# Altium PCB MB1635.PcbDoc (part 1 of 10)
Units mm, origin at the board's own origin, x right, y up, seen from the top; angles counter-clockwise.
Board outline 127 x 97 mm, 6 copper layers (Top Layer, Signal Layer 1, Signal Layer 2, Signal Layer 3, Signal Layer 4, Bottom Layer), stack 1.557 mm thick; 593 components, 478 nets, 2435 pads, 1743 vias.
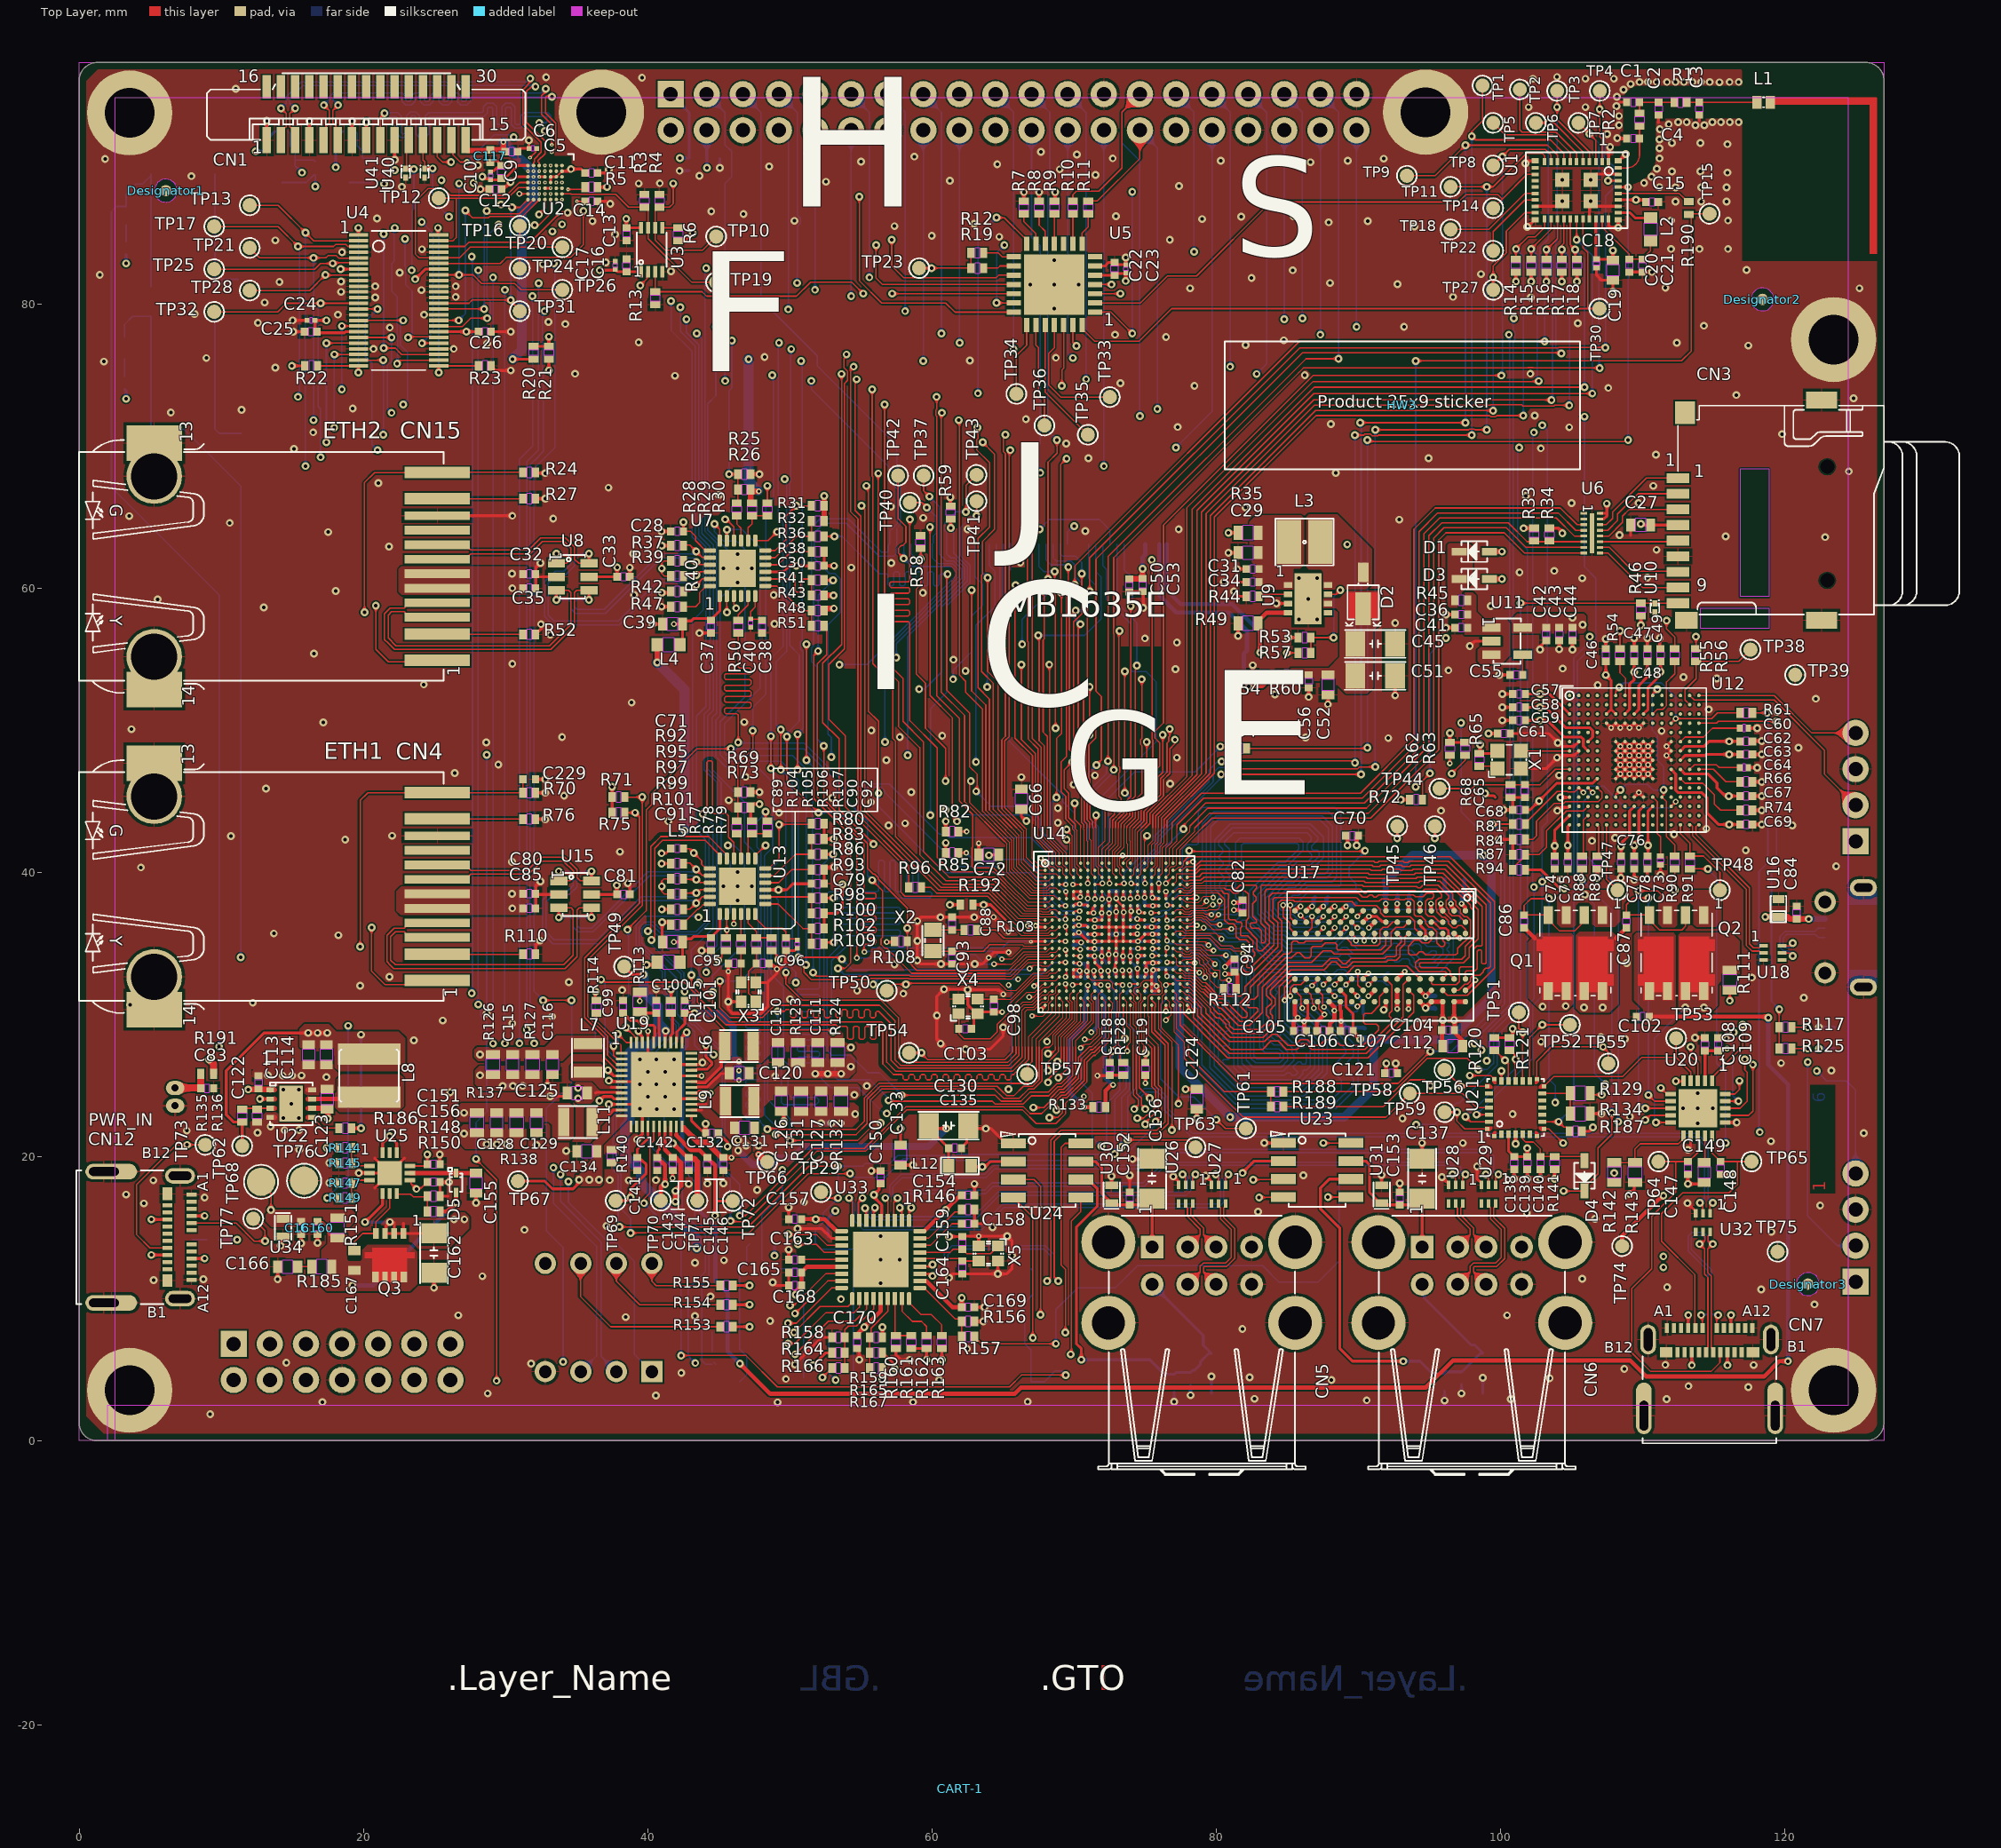
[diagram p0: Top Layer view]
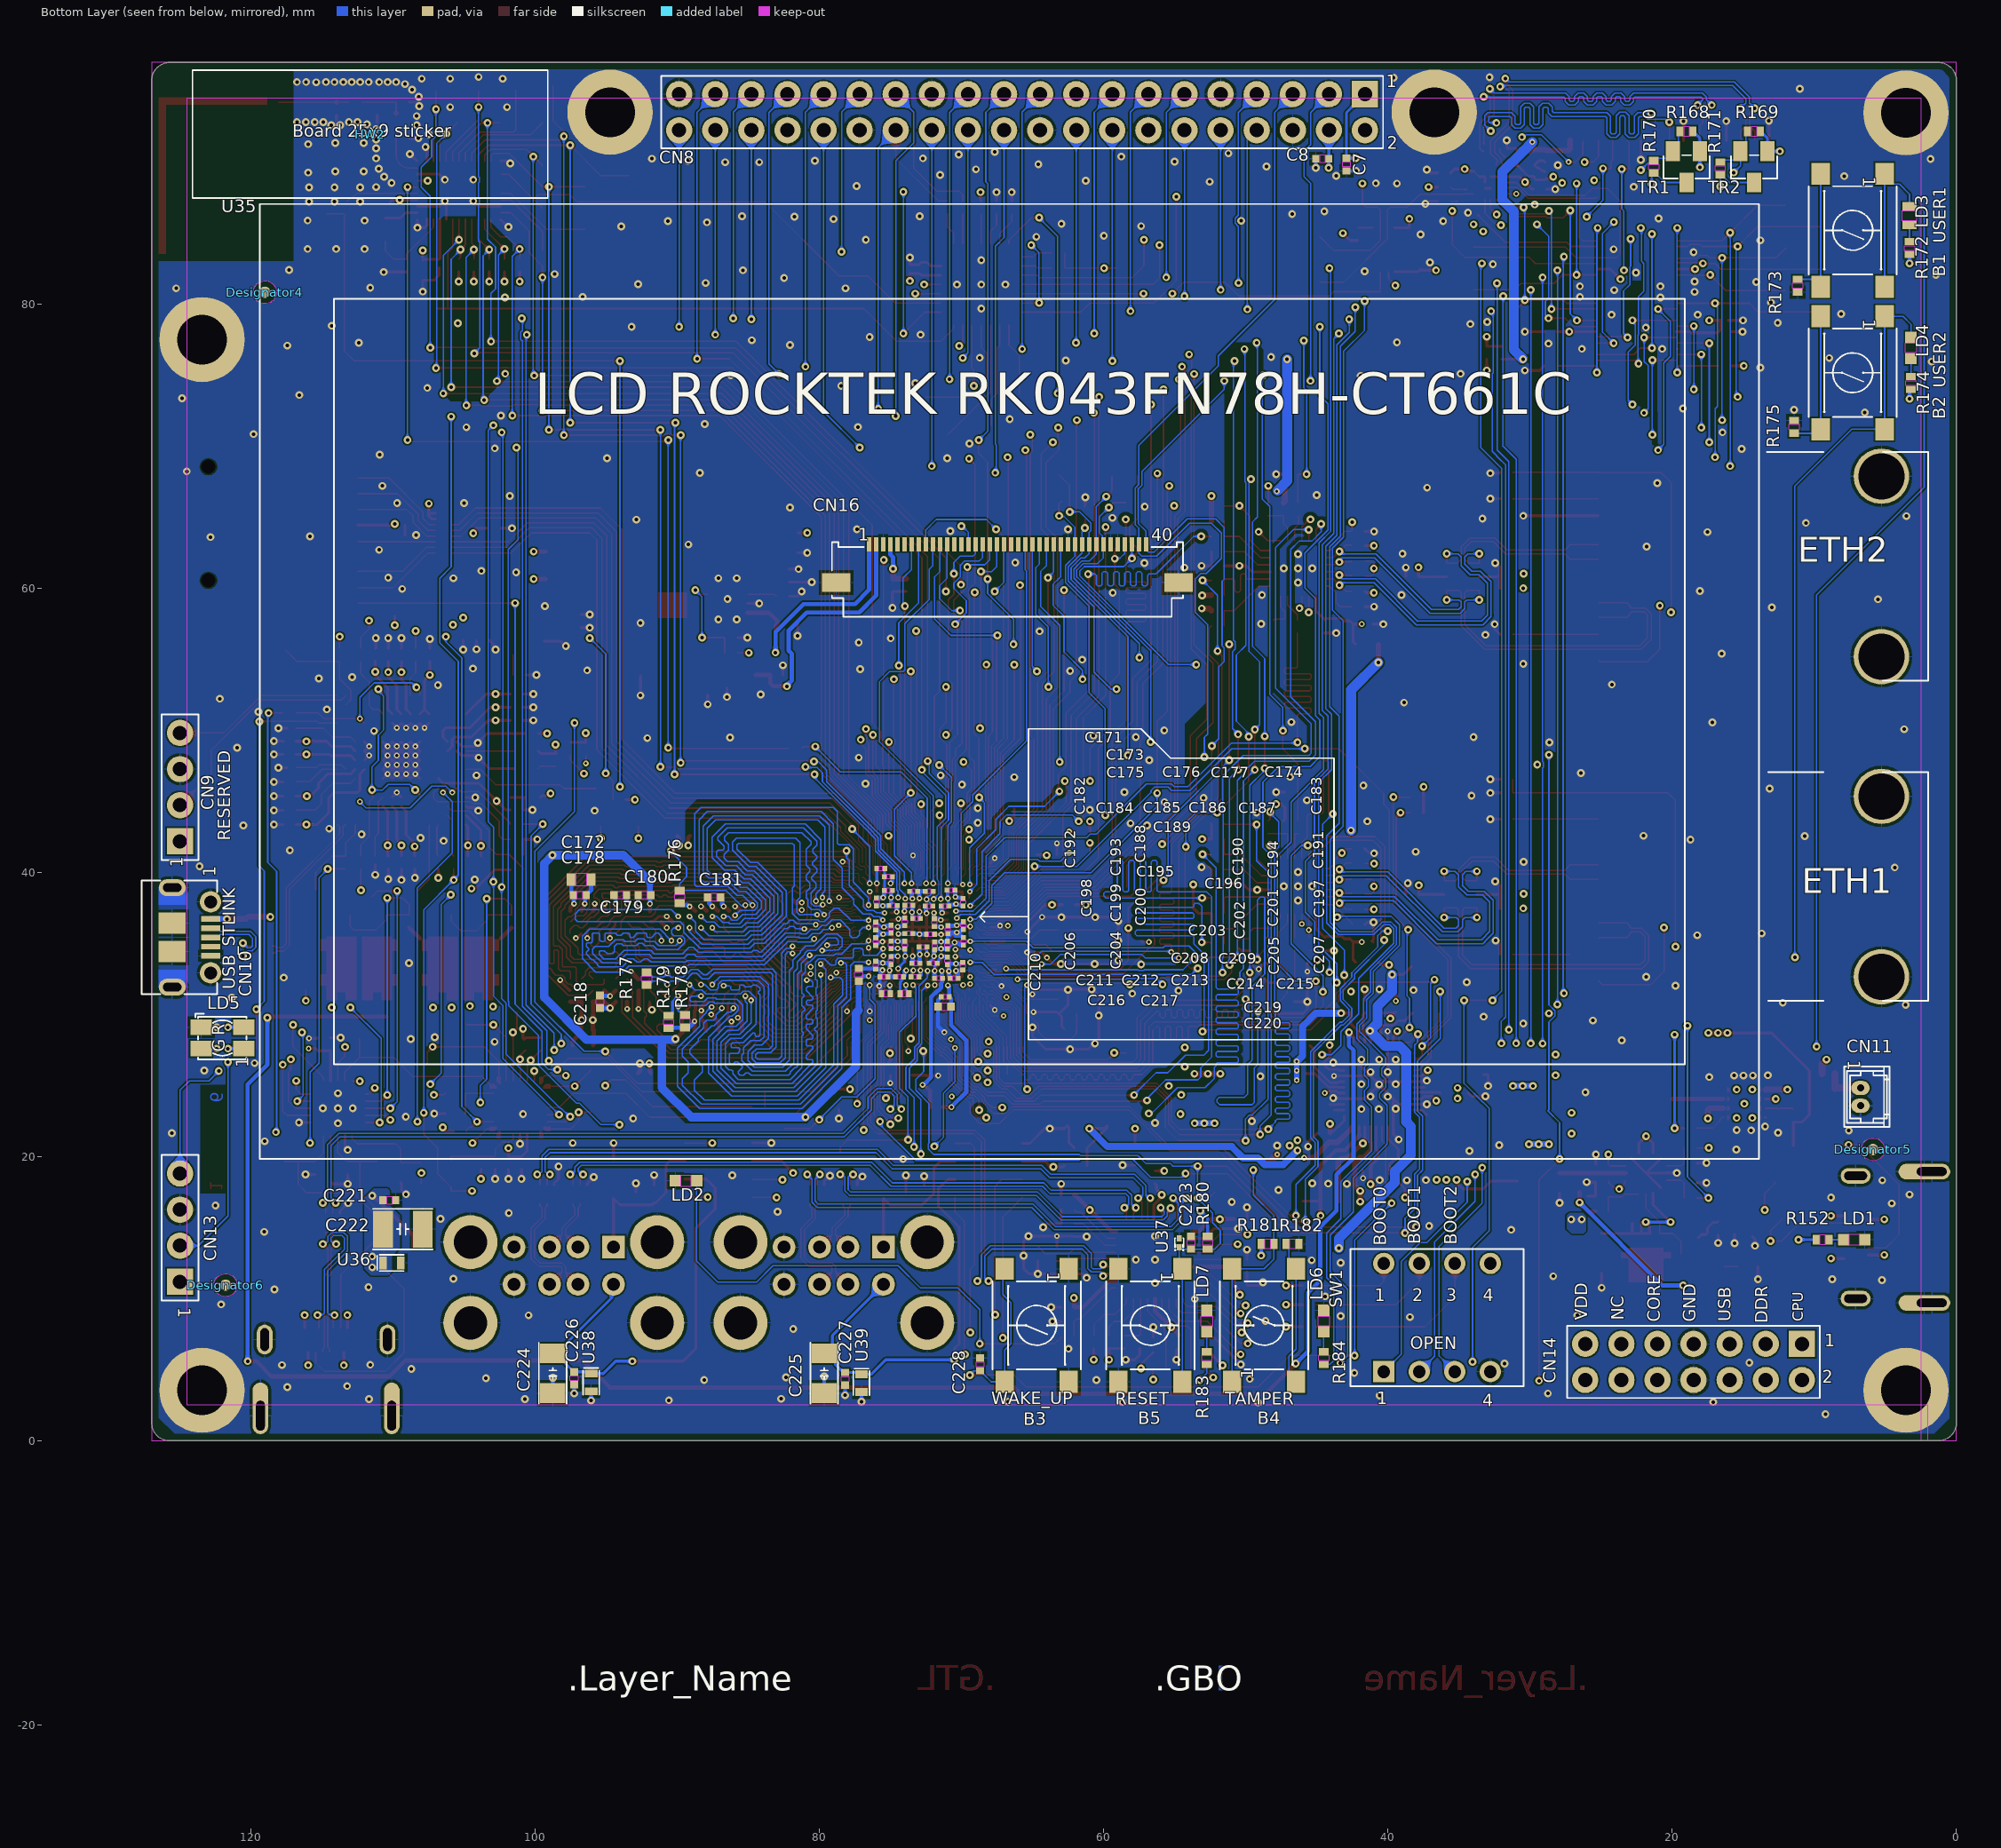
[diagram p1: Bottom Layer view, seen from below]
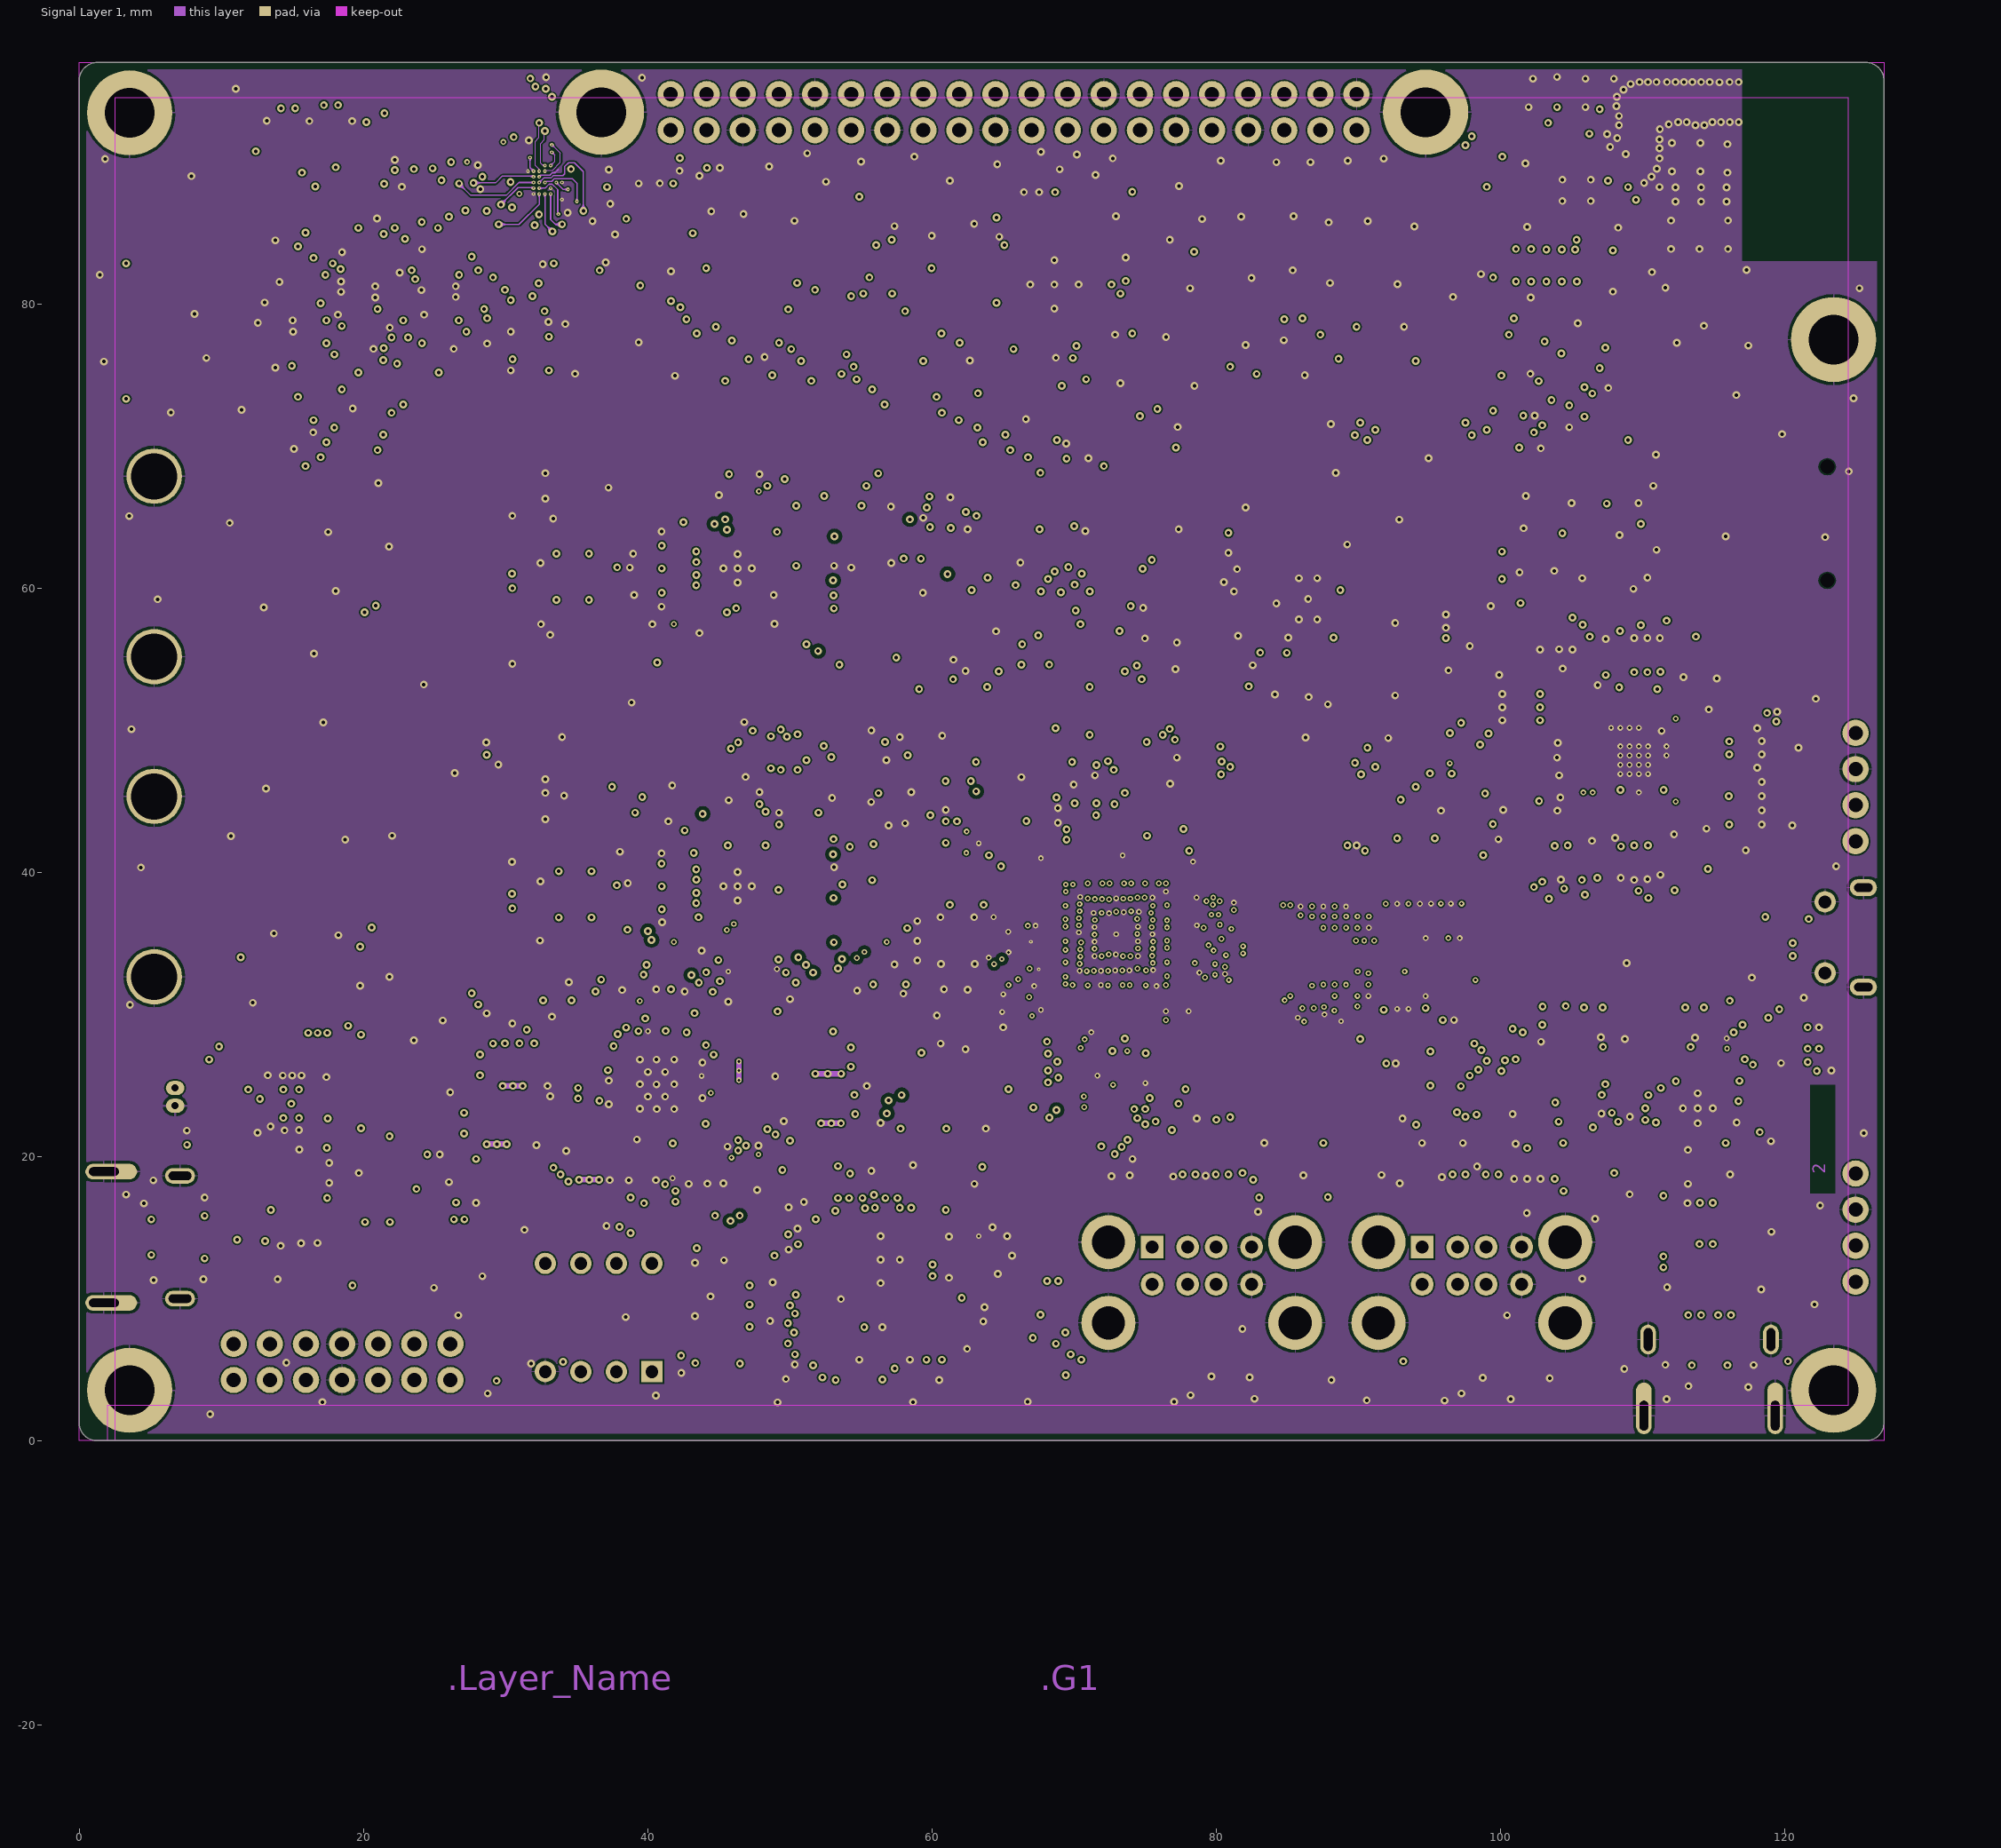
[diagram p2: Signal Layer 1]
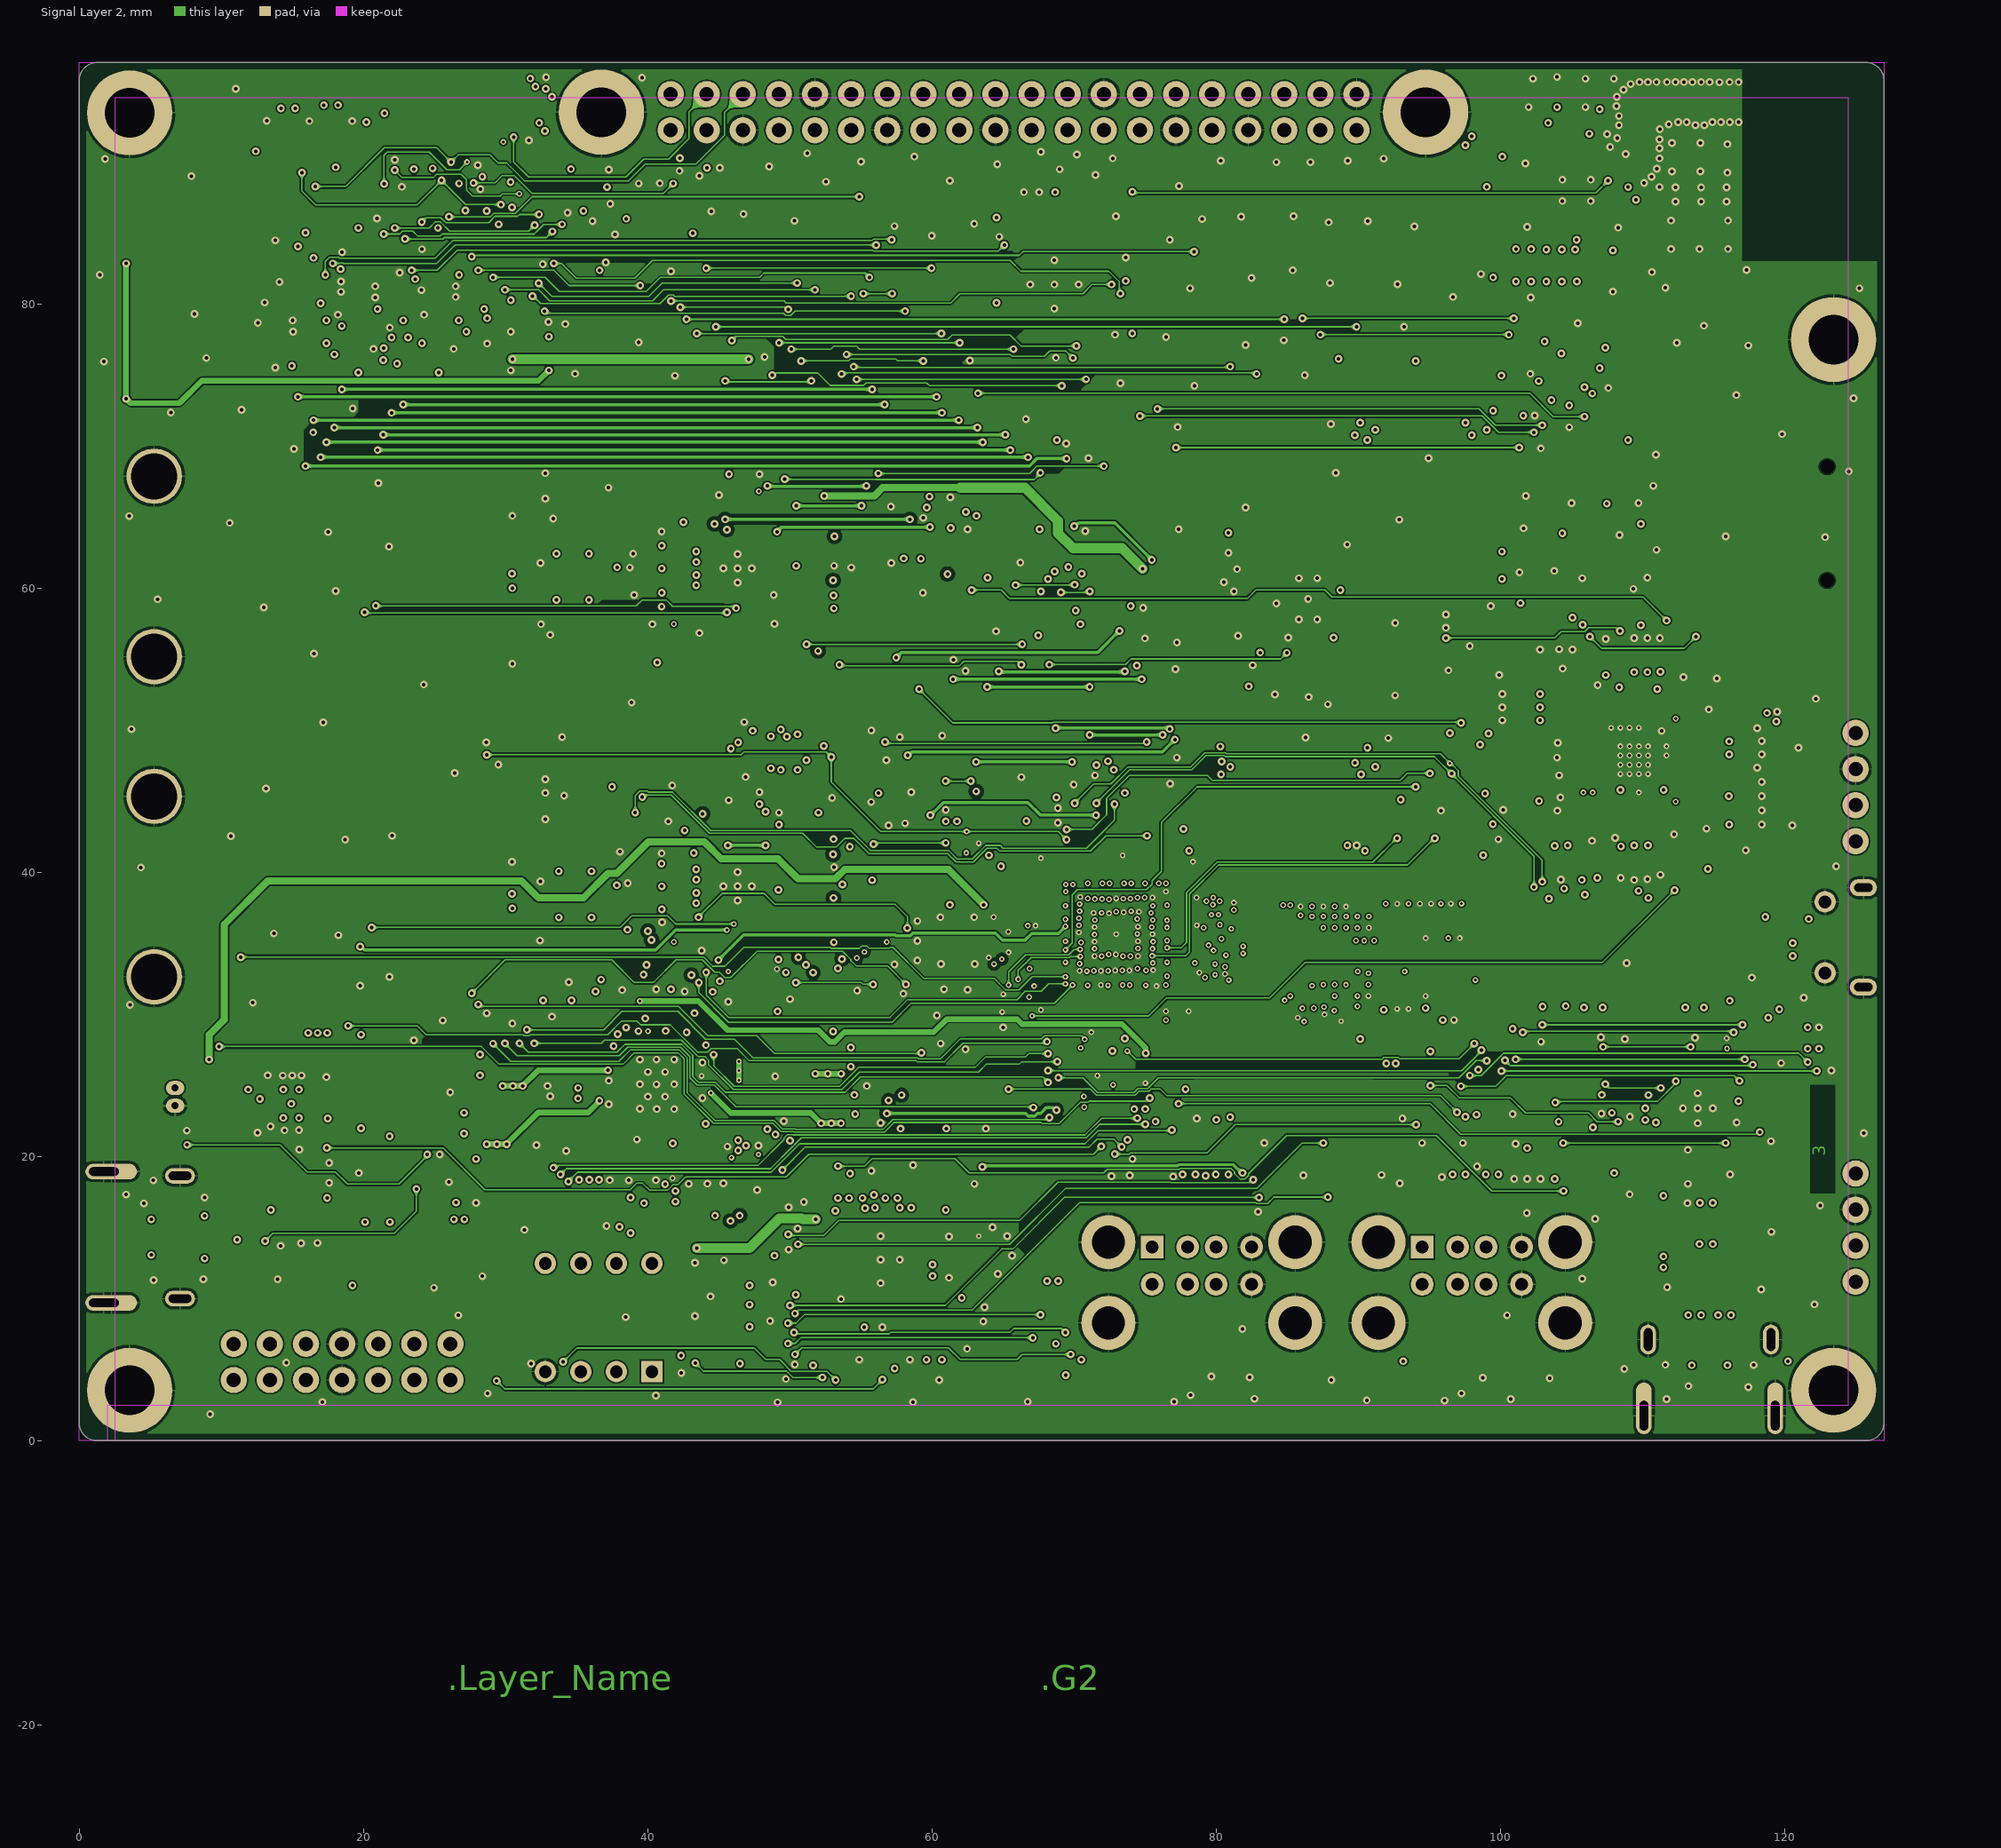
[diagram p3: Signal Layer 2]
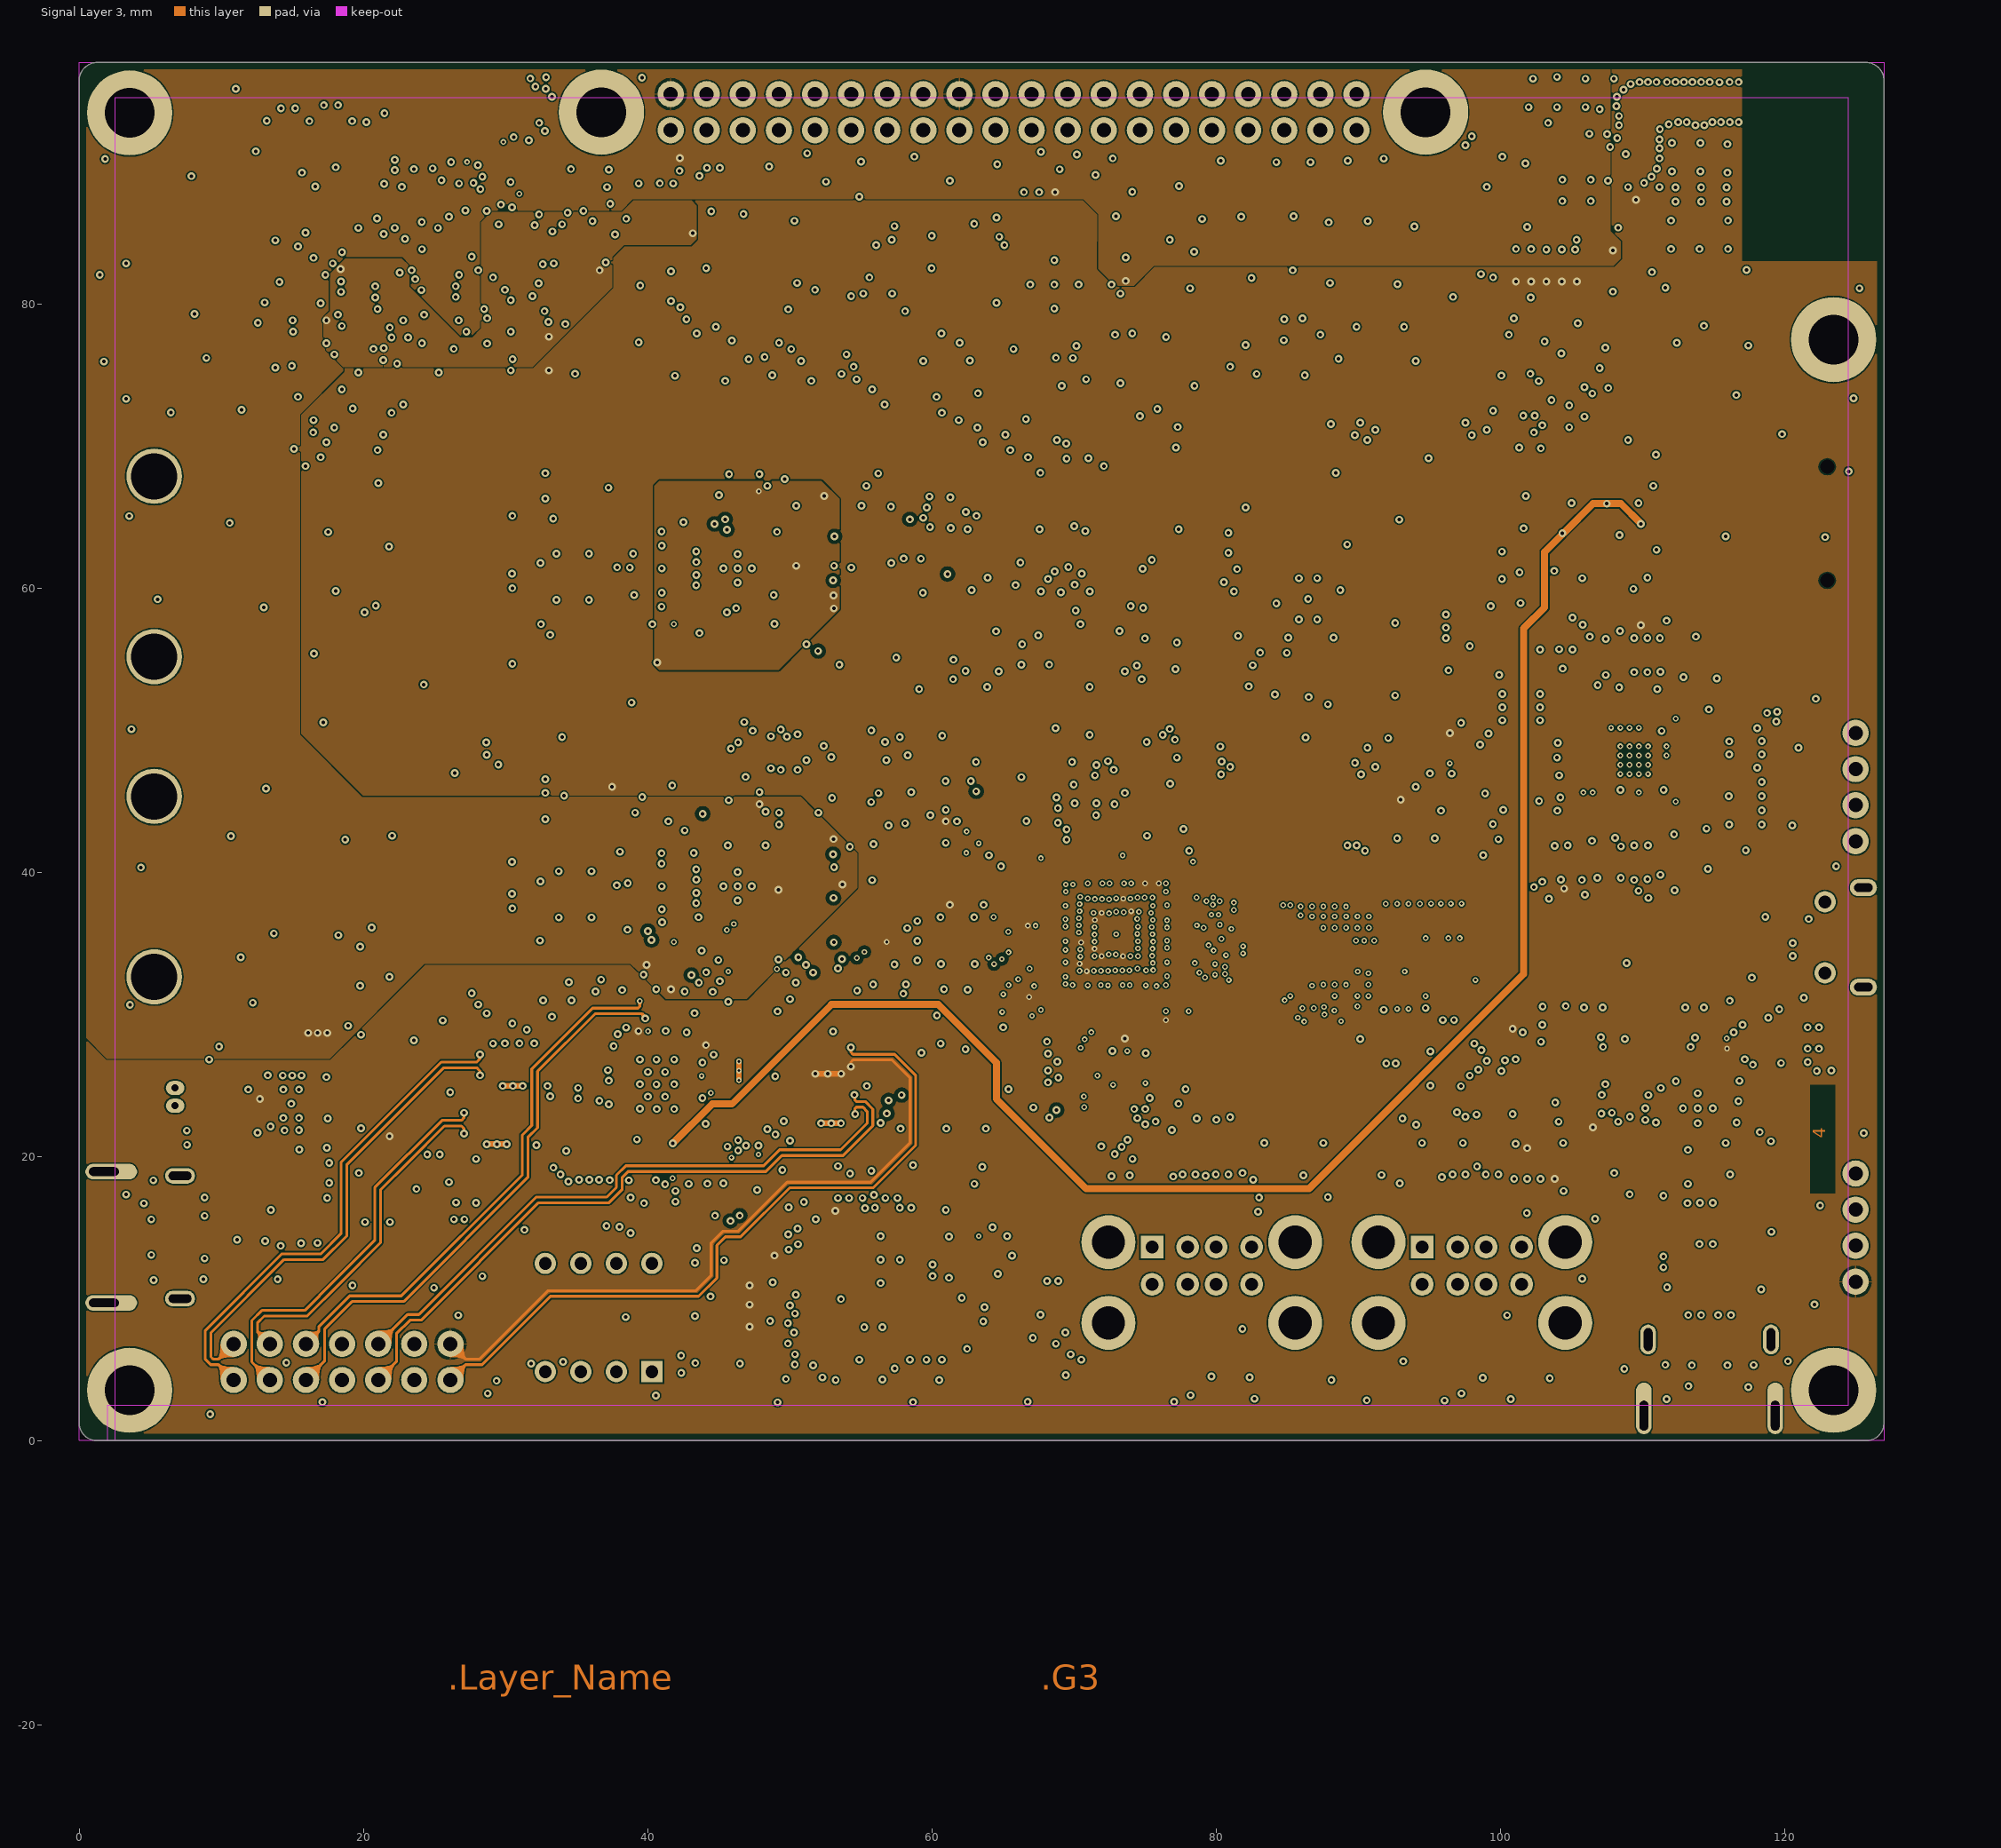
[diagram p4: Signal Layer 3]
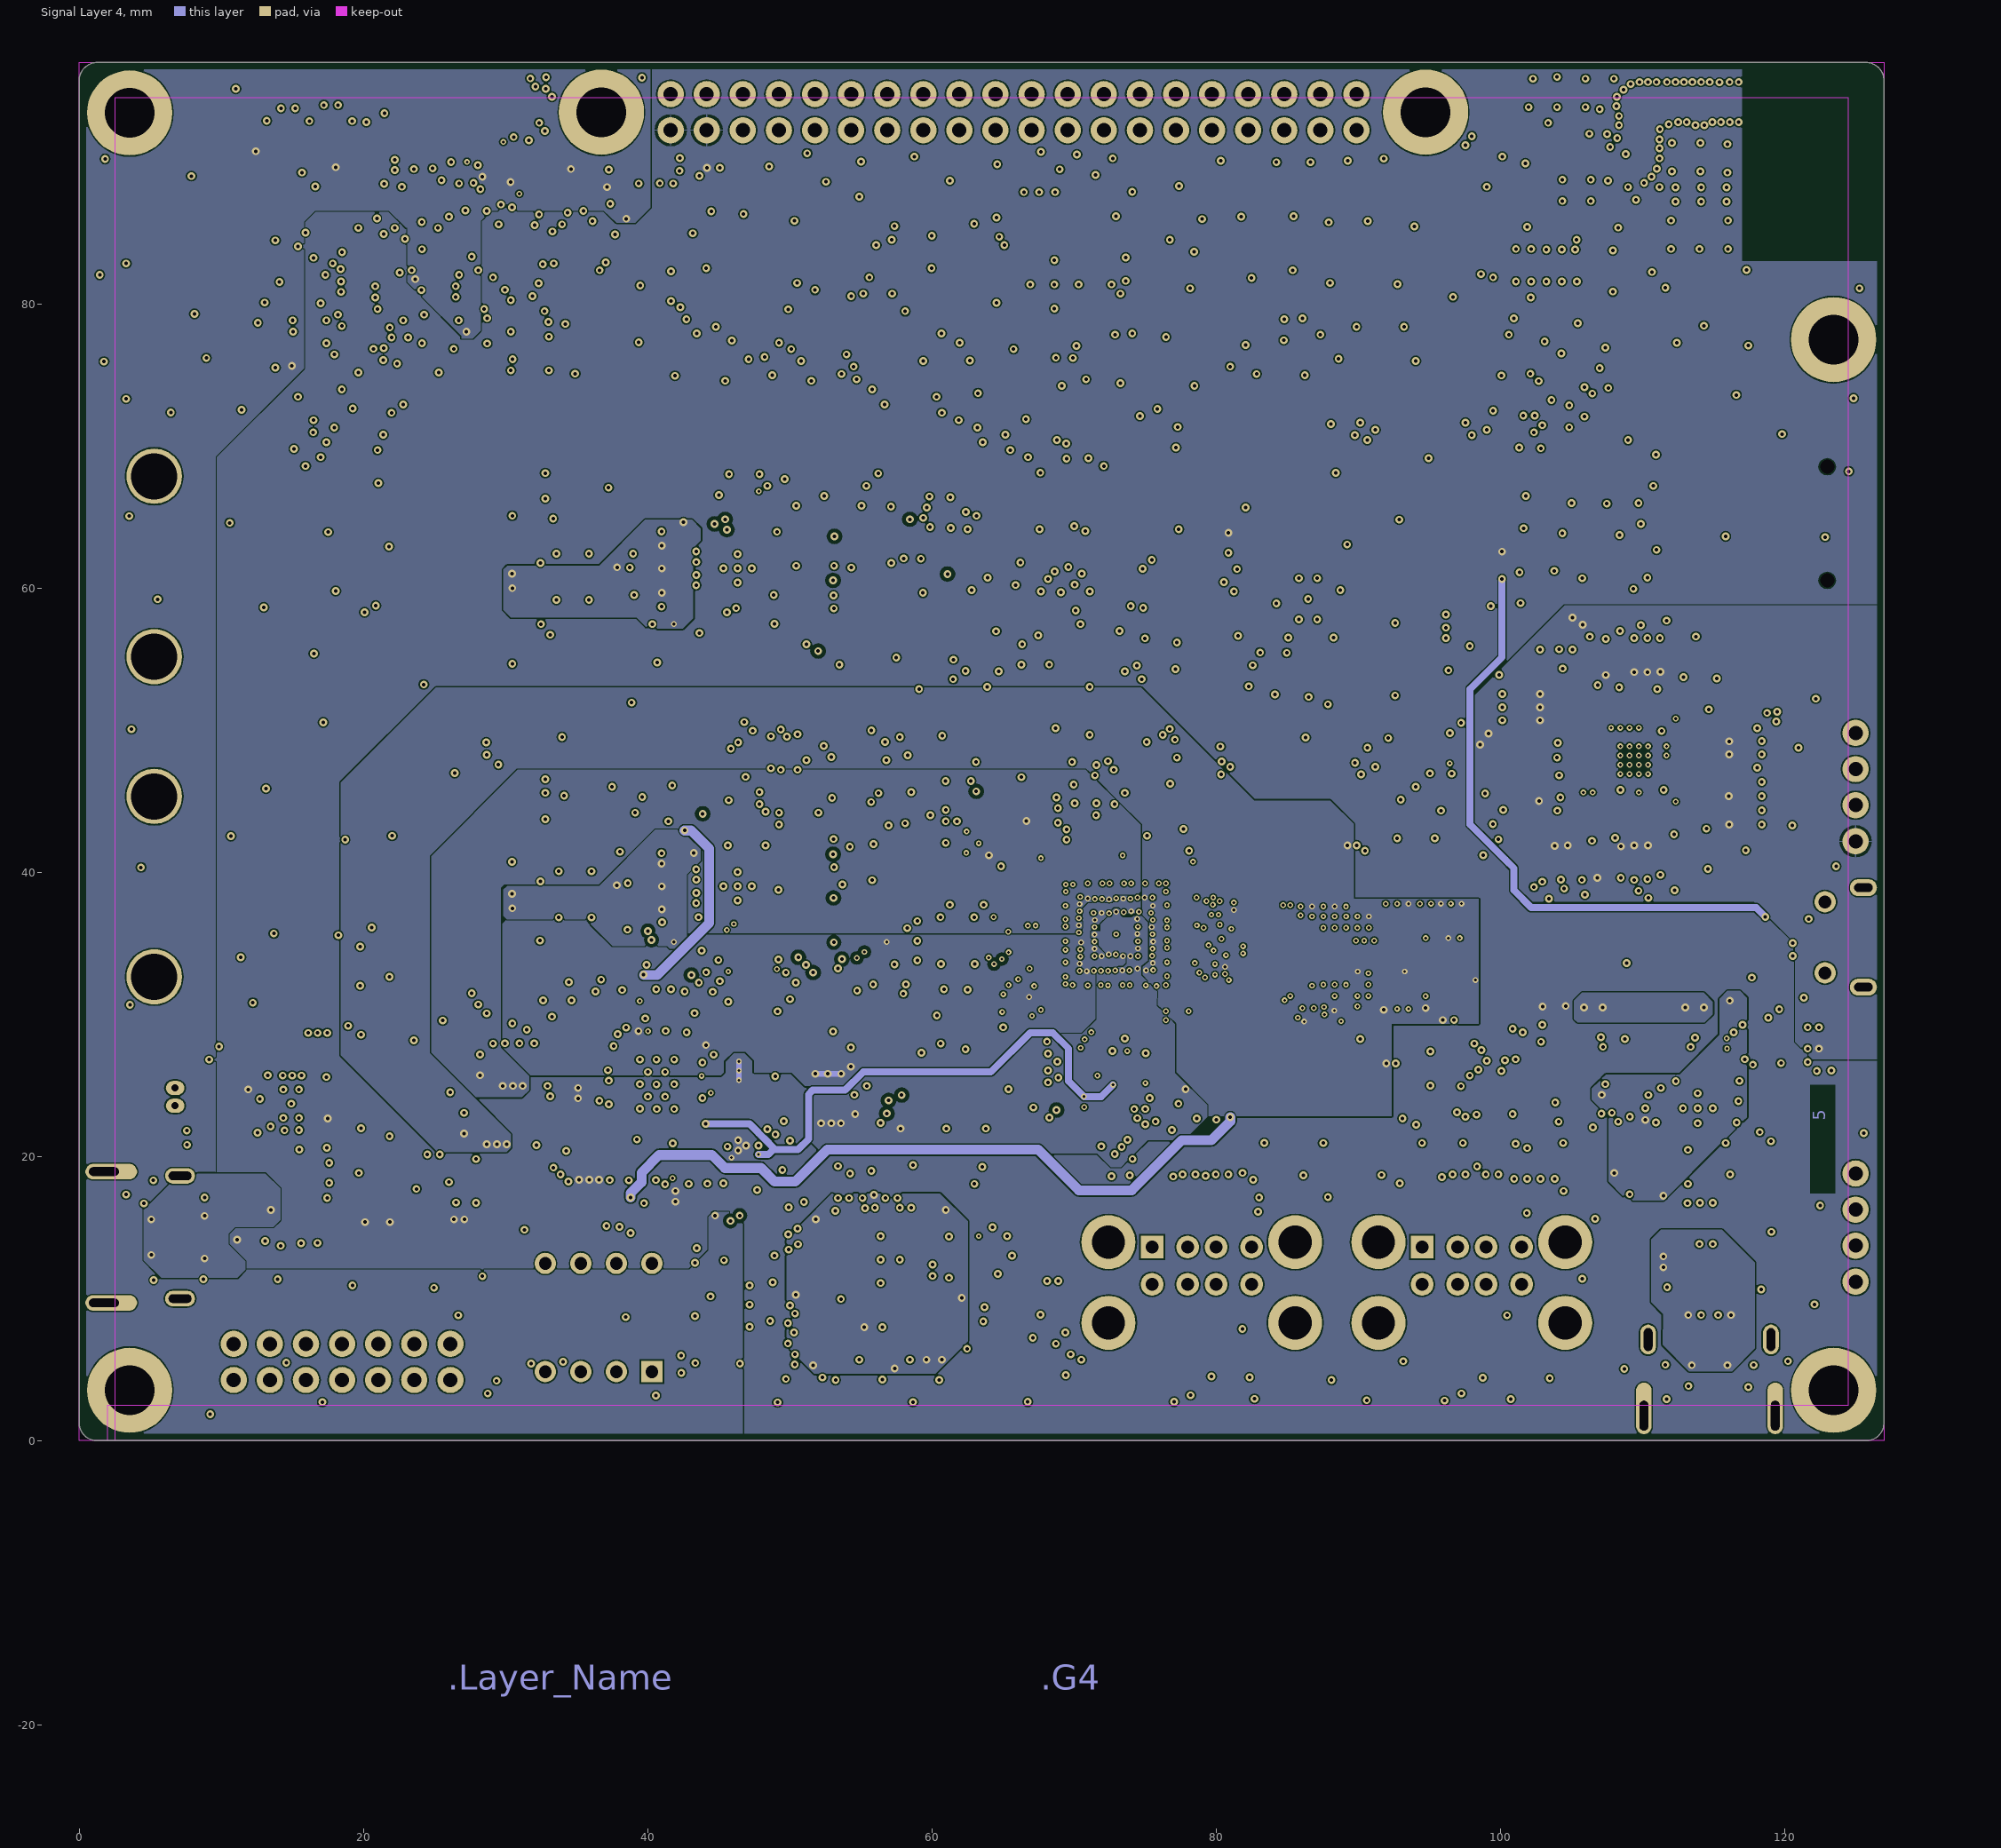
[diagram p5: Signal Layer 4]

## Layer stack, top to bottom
Top Solder: solder mask 0.025, Solder Resist, Dk 3.5
Top Layer: signal copper 0.027
Dielectric 1: prepreg 0.068, Dk 4
Signal Layer 1: signal copper 0.033
Dielectric 2: prepreg 0.51, Dk 4
Signal Layer 2: signal copper 0.033
Dielectric 3: core 0.215, Dk 5
Signal Layer 3: signal copper 0.033
Dielectric 4: prepreg 0.51, Dk 4
Signal Layer 4: signal copper 0.033
Dielectric5: prepreg 0.068, Dk 4
Bottom Layer: signal copper 0.027
Bottom Solder: solder mask 0.025, Solder Resist, Dk 3.5

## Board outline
0,1.27 0,95.73 cw(c1.27,95.73) 1.27,97 125.73,97 cw(c125.73,95.73) 127,95.73 127,1.27 cw(c125.73,1.27) 125.73,0 1.27,0 cw(c1.27,1.27)

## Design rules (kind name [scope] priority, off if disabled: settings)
BoardOutlineClearance [All] p1: gap=0.5 ignorepadtopadclearanceinfootprint=FALSE except(0: Arc-SplitContinuation Track-SplitContinuation SMDPad-SplitContinuation THPad-SplitContinuation Via-SplitContinuation Fill-SplitContinuation Poly-SplitContinuation Region-SplitContinuation Text-SplitContinuation)
Clearance Clearance_keepout_copper [KeepoutRestrictionsCopper] p1: gap=0 ignorepadtopadclearanceinfootprint=FALSE except(0.1: SMDPad-Fill SMDPad-Poly SMDPad-Region Fill-Fill Fill-Poly Fill-Region Poly-Poly Poly-Region Region-Region)
Clearance Clearance_keepout_track [KeepoutRestrictionsTrack] p2: gap=0 ignorepadtopadclearanceinfootprint=FALSE except(0.1: SMDPad-Fill SMDPad-Poly SMDPad-Region Fill-Fill Fill-Poly Fill-Region Poly-Poly Poly-Region Region-Region)
Clearance Clearance_MCU [WithinRoom('RoomDefinition')and TouchesRoom('RoomDefinition')] p3: gap=0.094 ignorepadtopadclearanceinfootprint=FALSE except(0: Arc-Hole Track-Hole SMDPad-Hole THPad-Hole Via-Hole Fill-Hole Poly-Hole Region-Hole Text-Hole; 0.1: Via-Via)
Clearance Clearance_DDR [WithinRoom('RoomDefinition_1')and TouchesRoom('RoomDefinition_1')] p4: gap=0.094 ignorepadtopadclearanceinfootprint=FALSE except(0: Arc-Hole Track-Hole SMDPad-Hole THPad-Hole Via-Hole Fill-Hole Poly-Hole Region-Hole Text-Hole; 0.1: Via-Via)
Clearance Clearance_SDMMC1 [InNetClass('SDMMC1') vs InNetClass('All Nets')] p5: gap=0.1 ignorepadtopadclearanceinfootprint=FALSE except(0: Arc-Hole Track-Hole SMDPad-Hole THPad-Hole Via-Hole Fill-Hole Poly-Hole Region-Hole Text-Hole; 0.15: Arc-Fill Track-Fill SMDPad-Fill THPad-Fill Via-Fill Fill-Fill; 0.2: THPad-THPad; 0.25: Track-Track)
Clearance Clearance_RGMII [InNetClass('RGMII_ETH_RXD_TXD')] p6: gap=0.1 ignorepadtopadclearanceinfootprint=FALSE except(0: Arc-Hole Track-Hole SMDPad-Hole THPad-Hole Via-Hole Fill-Hole Poly-Hole Region-Hole Text-Hole; 0.15: Arc-Fill Arc-Region Track-Fill Track-Region SMDPad-Fill SMDPad-Region THPad-Fill THPad-Region Via-Fill Via-Region Fill-Fill Fill-Region Poly-Region Region-Region; 0.2: Arc-THPad Track-THPad SMDPad-SMDPad SMDPad-THPad THPad-THPad; 0.26: Arc-Poly Track-Poly SMDPad-Poly THPad-Poly Via-Poly Fill-Poly Poly-Poly)
Clearance [All] p7: gap=0.1 ignorepadtopadclearanceinfootprint=FALSE except(0: Arc-Hole Track-Hole SMDPad-Hole THPad-Hole Via-Hole Fill-Hole Poly-Hole Region-Hole Text-Hole; 0.15: Arc-Fill Track-Fill SMDPad-Fill THPad-Fill Via-Fill Fill-Fill; 0.2: THPad-THPad)
ComponentClearance [HasFootprint('TP_SMD_1MM') vs HasFootprint('No Footprint')] p1: gap=0.2 collisioncheckmode=3 verticalgap=0.2 showdistances=FALSE
DiffPairsRouting I_SENSE [InDifferentialPairClass('I_SENSE')] p1: maxlimit=0.2 minlimit=0.2 mostfreqgap=0.2 toplayer_minwidth=0.09 toplayer_maxwidth=0.4 toplayer_prefwidth=0.2 midlayer1_minwidth=0.09 midlayer1_maxwidth=0.4 midlayer1_prefwidth=0.2 midlayer2_minwidth=0.09 midlayer2_maxwidth=0.4 midlayer2_prefwidth=0.2 midlayer3_minwidth=0.09 midlayer3_maxwidth=0.4 midlayer3_prefwidth=0.2 midlayer4_minwidth=0.09 midlayer4_maxwidth=0.4 midlayer4_prefwidth=0.2 bottomlayer_minwidth=0.09 bottomlayer_maxwidth=0.4 bottomlayer_prefwidth=0.2 maxuncoupledlength=12.7
DiffPairsRouting DiffPairsRouting_DIFF_100Ohms [InDifferentialPairClass('Diff_100Ohms')] p2: maxlimit=0.3 minlimit=0.127 mostfreqgap=0.3 toplayer_mingap=0.17 toplayer_maxgap=0.17 toplayer_prefgap=0.17 toplayer_minwidth=0.09 toplayer_maxwidth=0.09 toplayer_prefwidth=0.09 midlayer1_mingap=0.25 midlayer1_minwidth=0.075 midlayer1_maxwidth=0.075 midlayer1_prefwidth=0.075 midlayer2_maxgap=0.127 midlayer2_prefgap=0.127 midlayer2_minwidth=0.075 midlayer2_maxwidth=0.075 midlayer2_prefwidth=0.075 midlayer3_maxgap=0.127 midlayer3_prefgap=0.127 midlayer3_minwidth=0.075 midlayer3_maxwidth=0.075 midlayer3_prefwidth=0.075 midlayer4_mingap=0.3 midlayer4_minwidth=0.075 midlayer4_maxwidth=0.075 midlayer4_prefwidth=0.075 bottomlayer_mingap=0.17 bottomlayer_maxgap=0.17 bottomlayer_prefgap=0.17 bottomlayer_minwidth=0.09 bottomlayer_maxwidth=0.09 bottomlayer_prefwidth=0.09 impedanceprofiledriven=TRUE impedanceprofileid={5577E63A-EB22-4F3A-99DF-7BFE230ABC16} impedanceprofilevalue=100.000000 maxuncoupledlength=12.7
DiffPairsRouting DiffPairsRouting_USB_90Ohms [InDifferentialPairClass('USB_90Ohms')] p3: maxlimit=0.13 minlimit=0.127 mostfreqgap=0.127 toplayer_mingap=0.13 toplayer_prefgap=0.13 toplayer_minwidth=0.1 toplayer_maxwidth=0.1 toplayer_prefwidth=0.1 midlayer1_maxgap=0.127 midlayer1_minwidth=0.066 midlayer1_maxwidth=0.066 midlayer1_prefwidth=0.066 midlayer2_maxgap=0.127 midlayer2_minwidth=0.113 midlayer2_maxwidth=0.113 midlayer2_prefwidth=0.113 midlayer3_maxgap=0.127 midlayer3_minwidth=0.113 midlayer3_maxwidth=0.113 midlayer3_prefwidth=0.113 midlayer4_maxgap=0.127 midlayer4_minwidth=0.066 midlayer4_maxwidth=0.066 midlayer4_prefwidth=0.066 bottomlayer_mingap=0.13 bottomlayer_prefgap=0.13 bottomlayer_minwidth=0.1 bottomlayer_maxwidth=0.1 bottomlayer_prefwidth=0.1 impedanceprofiledriven=TRUE impedanceprofileid={A0CE1C67-AEA5-4110-ADE4-376356967360} impedanceprofilevalue=90.000000 maxuncoupledlength=12.7
FanoutControl Fanout_BGA [IsBGA] p1: bgadir=Out bgaviamode=Closest fanoutstyle=Auto fanoutdirection=Alternating viagrid=0.025 // Fanout_BGA (Default Rule)
FanoutControl Fanout_LCC [IsLCC] p2: bgadir=Out bgaviamode=Closest fanoutstyle=Auto fanoutdirection=Alternating viagrid=0.025 // Fanout_LCC (Default Rule)
FanoutControl Fanout_SOIC [IsSOIC] p3: bgadir=Out bgaviamode=Closest fanoutstyle=Auto fanoutdirection=Alternating viagrid=0.025 // Fanout_SOIC (Default Rule)
FanoutControl Fanout_Small [(CompPinCount < 5)] p4: bgadir=Out bgaviamode=Closest fanoutstyle=Auto fanoutdirection=OutThenIn viagrid=0.025 // Fanout_Small (Default Rule)
FanoutControl Fanout_Default [All] p5: bgadir=Out bgaviamode=Closest fanoutstyle=Auto fanoutdirection=Alternating viagrid=0.025 // Fanout_Default (Default Rule)
HoleSize [All] p1: absolutevalues=TRUE maxlimit=10 minlimit=0.025 maxpercent=80.000 minpercent=20.000
HoleToHoleClearance [All] p1: gap=0.25 allowstackedmicrovias=TRUE
Length Length_SDMMC1 [InNetClass('SDMMC1')] p1: maxlimit=100 minlimit=0
MatchedLengths "Schematic Matched Net Lengths_9" [InNetClass('LCD_R[2..7]')] p1: tolerance=2.54 checknetsindiffpair=FALSE checkdiffpairvsdiffpair=TRUE checkxsignals=TRUE checkothers=TRUE
MatchedLengths "Schematic Matched Net Lengths_8" [InNetClass('LCD_B[2..7]')] p2: tolerance=2.54 checknetsindiffpair=FALSE checkdiffpairvsdiffpair=TRUE checkxsignals=TRUE checkothers=TRUE
MatchedLengths "Schematic Matched Net Lengths_7" [InNetClass('LCD_G[2..7]')] p3: tolerance=2.54 checknetsindiffpair=FALSE checkdiffpairvsdiffpair=TRUE checkxsignals=TRUE checkothers=TRUE
MatchedLengths "Schematic Matched Net Lengths_6" [InNet('LCD_VSYNC')] p4: tolerance=2.54 checknetsindiffpair=FALSE checkdiffpairvsdiffpair=TRUE checkxsignals=TRUE checkothers=TRUE
MatchedLengths "Schematic Matched Net Lengths_5" [InNet('LCD_CLK')] p5: tolerance=2.54 checknetsindiffpair=FALSE checkdiffpairvsdiffpair=TRUE checkxsignals=TRUE checkothers=TRUE
MatchedLengths "Schematic Matched Net Lengths_4" [InNet('LCD_HSYNC')] p6: tolerance=2.54 checknetsindiffpair=FALSE checkdiffpairvsdiffpair=TRUE checkxsignals=TRUE checkothers=TRUE
MatchedLengths "Schematic Matched Net Lengths_3" [InNet('USB_DEV_HS_CN_N')] p7: tolerance=2 checknetsindiffpair=TRUE checkdiffpairvsdiffpair=FALSE checkxsignals=FALSE checkothers=FALSE
MatchedLengths "Schematic Matched Net Lengths_2" [InNet('USB_DEV_HS_N')] p8: tolerance=2 checknetsindiffpair=TRUE checkdiffpairvsdiffpair=FALSE checkxsignals=FALSE checkothers=FALSE
MatchedLengths "Schematic Matched Net Lengths_1" [InNet('USB_DEV_HS_CN_P')] p9: tolerance=2 checknetsindiffpair=TRUE checkdiffpairvsdiffpair=FALSE checkxsignals=FALSE checkothers=FALSE
MatchedLengths "Schematic Matched Net Lengths" [InNet('USB_DEV_HS_P')] p10: tolerance=2 checknetsindiffpair=TRUE checkdiffpairvsdiffpair=FALSE checkxsignals=FALSE checkothers=FALSE
MatchedLengths MatchedLengths_ETH1 [InxSignalClass('RGMII_ETH1')] p11: tolerance=10 checknetsindiffpair=FALSE checkdiffpairvsdiffpair=TRUE checkxsignals=TRUE checkothers=TRUE
MatchedLengths MatchedLengths_ETH2 [InxSignalClass('RGMII_ETH2')] p12: tolerance=10 checknetsindiffpair=FALSE checkdiffpairvsdiffpair=TRUE checkxsignals=TRUE checkothers=TRUE
MatchedLengths MatchedLengths_SDMMC1 [InxSignalClass('SDMMC1')] p13: tolerance=5 checknetsindiffpair=FALSE checkdiffpairvsdiffpair=TRUE checkxsignals=TRUE checkothers=TRUE
MaxMinImpedance "Schematic Impedance Constraint_7" [InNet('USB_DEV_HS_N')] p1: minimum=85.00 maximum=95.00
MaxMinImpedance "Schematic Impedance Constraint_6" [InNet('USB_DEV_HS_CN_P')] p2: minimum=85.00 maximum=95.00
MaxMinImpedance "Schematic Impedance Constraint_5" [InNet('USB_DEV_HS_P')] p3: minimum=85.00 maximum=95.00
MaxMinImpedance "Schematic Impedance Constraint_4" [InNet('USB_DEV_HS_CN_N')] p4: minimum=85.00 maximum=95.00
MaxMinImpedance "Schematic Impedance Constraint_3" [InNet('USB_DEV_HS_CN_P')] p5: minimum=85.00 maximum=95.00
MaxMinImpedance "Schematic Impedance Constraint_1" [InNet('USB_DEV_HS_CN_N')] p6: minimum=85.00 maximum=95.00
MaxMinImpedance "Schematic Impedance Constraint_2" [InNet('USB_DEV_HS_N')] p7: minimum=85.00 maximum=95.00
MaxMinImpedance "Schematic Impedance Constraint" [InNet('USB_DEV_HS_P')] p8: minimum=85.00 maximum=95.00
MinimumSolderMaskSliver [All] p1: minsoldermaskwidth=0.1
PlaneConnect [All] p1: planeconnectstyle=Relief reliefexpansion=0.508 reliefentries=4 reliefconductorwidth=0.21 reliefairgap=0.21
PolygonConnect PolygonConnect_NO_FT [IsNamedPolygon('NO_FT')] p1: connectstyle=Direct reliefconductorwidth=0.254 reliefentries=4 polygonreliefangle="90 Angle" airgapwidth=0.254
PolygonConnect [All] p2: thpad.connectstyle=Relief thpad.reliefconductorwidth=0.1 thpad.reliefentries=4 thpad.polygonreliefangle="90 Angle" thpad.airgapwidth=0.2 smdpad.connectstyle=Relief smdpad.reliefconductorwidth=0.1 smdpad.reliefentries=4 smdpad.polygonreliefangle="90 Angle" smdpad.airgapwidth=0.2 via.connectstyle=Direct via.reliefconductorwidth=0.2 via.reliefentries=4 via.polygonreliefangle="90 Angle" via.airgapwidth=0.2
RoomDefinition [InComponentClass('Room Definition 1') vs False] p1: confinementstyle=ConfineIn formatcopy=TRUE lockcomponents=FALSE outline 65.175,43.125 81.275,43.125 81.275,27.725 65.175,27.725
RoomDefinition RoomDefinition_1 [InComponentClass('Components Class 1')] p2: confinementstyle=ConfineIn formatcopy=TRUE lockcomponents=FALSE outline 74.9,40.7 79.1,44.9 88.375,44.9 92.175,41.1 97.15,41.1 99.625,38.625 99.625,31.4 96.4,28.175 92.85,28.175 91.025,26.35 91.025,24.625 89.425,23.025 81,23.025 77.638,26.388 77.638,29.884 74.9,32.621
RoutingVias [All] p1: holewidth=0.2 width=0.4 viastyle="Through Hole" minholewidth=0.1 minwidth=0.2 maxholewidth=0.35 maxwidth=0.55
ShortCircuit ShortCircuit_LNK2 [InPadClass('LNK2')] p1: allowed=TRUE
ShortCircuit ShortCircuit_LNK1 [InPadClass('LNK1')] p2: allowed=TRUE
ShortCircuit [All] p3: allowed=FALSE
SilkToSilkClearance [All] p1: silktosilkclearance=0.2
SilkToSolderMaskClearance [IsPad] p1: minsilkscreentomaskgap=0.2 clearancetoexposedcopper=TRUE
SolderMaskExpansion [All] p1: expansion=0.1 istentingtop=FALSE
Width Width_MCU [WithinRoom('RoomDefinition')and TouchesRoom('RoomDefinition')] p1: maxlimit=10 minlimit=0.075 preferedwidth=0.09 toplayer_prefwidth=0.075 minimp=50.000000 maximp=50.000000 favimp=50.000000
Width Width_50Ohms [InNetClass('50_Ohms')] p2: maxlimit=0.219 minlimit=0.077 preferedwidth=0.219 toplayer_minwidth=0.1 toplayer_maxwidth=0.1 toplayer_prefwidth=0.1 midlayer1_maxwidth=0.077 midlayer1_prefwidth=0.077 midlayer2_minwidth=0.219 midlayer3_minwidth=0.219 midlayer4_maxwidth=0.077 midlayer4_prefwidth=0.077 bottomlayer_minwidth=0.1 bottomlayer_maxwidth=0.1 bottomlayer_prefwidth=0.1 impedanceprofiledriven=TRUE impedanceprofileid={CEAE712B-4FFB-4667-9AAD-FAB2F10F3795} impedanceprofilevalue=50.000000 minimp=50.000000 maximp=50.000000 favimp=50.000000
Width Width_ALIMS [InNetClass('ALIMS')] p3: maxlimit=10 minlimit=0.09 preferedwidth=0.2
Width [All] p4: maxlimit=10 minlimit=0.075 preferedwidth=0.1
16 further rules are at their usual default settings.

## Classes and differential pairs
component class U_USB_TypeC_DRP: TP78
component class U_Peripherals: HW1301 HW1302 HW1303
net class LTDC: LCD_B2 LCD_B3 LCD_B4 LCD_B5 LCD_B6 LCD_B7 LCD_CLK LCD_G2 LCD_G3 LCD_G4 LCD_G5 LCD_G6 LCD_G7 LCD_HSYNC LCD_R2 LCD_R3 LCD_R4 LCD_R5 LCD_R6 LCD_R7 LCD_VSYNC
net class 50_Ohms: DCMI_D0 DCMI_D1 DCMI_D2 DCMI_D3 DCMI_D4 DCMI_D5 DCMI_D6 DCMI_D7 DCMI_HSYNC DCMI_PIXCLK DCMI_VSYNC ETH1_CLK ETH1_CRS_DV ETH1_MDC ETH1_MDINT ETH1_MDIO ETH1_RX_CLK ETH1_RXD0 ETH1_RXD1 ETH1_TX_EN ETH1_TXD0 ETH1_TXD1 ETH2_CLK ETH2_CRS_DV ETH2_MDC ETH2_MDINT ETH2_MDIO ETH2_RXD0 ETH2_RXD1 ETH2_TX_EN ETH2_TXD0 ETH2_TXD1 LCD_B2 LCD_B3 LCD_B4 LCD_B5 LCD_B6 LCD_B7 LCD_CLK LCD_G2 LCD_G3 LCD_G4 LCD_G5 LCD_G6 LCD_G7 LCD_HSYNC LCD_R2 LCD_R3 LCD_R4 LCD_R5 LCD_R6 LCD_R7 LCD_VSYNC NetC229_2 NetCN3_1 NetCN3_2 NetCN3_5 NetCN3_7 NetCN3_8 NetR29_1 NetR32_1 NetR41_2 NetR48_1 NetR50_2 NetR78_1 NetR83_1 NetR98_2 NetR102_1 NetR106_2 SDMMC1_CK SDMMC1_D0 SDMMC1_D1 SDMMC1_D2 SDMMC1_D3 SDMMC2_CK SDMMC2_D0 SDMMC2_D1 SDMMC2_D2 SDMMC2_D3 T_SWCLK T_SWDIO T_SWO
net class ALIMS: 1V8_PERIPH 3V3_AO 3V3_STLK 3V3_SW 5V_USB_CHGR 5V_VIN GND NetC83_2 VDD VDD_ADC VDD_CORE VDD_CPU VDD_DDR VDD_LS VDD_SD VDD_USB VREF_DDR
differential pair class USB_90Ohms: USB1CN25 USB2CN25 USB3CN26 USB4CN26 USB_D1 USB_D2 USB_DCONN USB_DEV_HS USB_DEV_HS_CN USBDN1 USBDN2 USBDN3 USBDN4
net class SDMMC1: NetCN3_1 NetCN3_2 NetCN3_5 NetCN3_7 NetCN3_8 SDMMC1_CK SDMMC1_D0 SDMMC1_D1 SDMMC1_D2 SDMMC1_D3
net class RGMII_ETH_RXD_TXD: ETH1_CRS_DV ETH1_RXD0 ETH1_RXD1 ETH1_TX_EN ETH1_TXD0 ETH1_TXD1 ETH2_CRS_DV ETH2_RXD0 ETH2_RXD1 ETH2_TX_EN ETH2_TXD0 ETH2_TXD1
net class RGMII_ETH1: ETH1_CLK ETH1_CRS_DV ETH1_MDC ETH1_MDINT ETH1_MDIO ETH1_RX_CLK ETH1_RXD0 ETH1_RXD1 ETH1_TX_EN ETH1_TXD0 ETH1_TXD1 NetC229_2 NetR78_1 NetR83_1 NetR98_2 NetR102_1 NetR106_2
net class RGMII_ETH2: ETH2_CLK ETH2_CRS_DV ETH2_MDC ETH2_MDINT ETH2_MDIO ETH2_RXD0 ETH2_RXD1 ETH2_TX_EN ETH2_TXD0 ETH2_TXD1 NetR29_1 NetR32_1 NetR41_2 NetR48_1 NetR50_2
differential pair class Diff_100Ohms: CLK1 DATA1 DATA2 DDR_CLK DDR_DQS0 DDR_DQS1 RD1 RD2 TD1 TD2
differential pair CLK1: +CLK_P -CLK_N
differential pair DATA2: +DATA2_P -DATA2_N
differential pair DATA1: +DATA1_P -DATA1_N
differential pair USB_D1: +USB_D1_P -USB_D1_N
differential pair USBDN4: +USBDN4_P -USBDN4_N
differential pair USBDN3: +USBDN3_P -USBDN3_N
differential pair USBDN2: +USBDN2_P -USBDN2_N
differential pair USBDN1: +USBDN1_P -USBDN1_N
differential pair USB_DEV_HS: +USB_DEV_HS_P -USB_DEV_HS_N
differential pair USB_DEV_HS_CN: +USB_DEV_HS_CN_P -USB_DEV_HS_CN_N
differential pair USB_DCONN: +USB_DCONN_P -USB_DCONN_N
differential pair USB_D2: +USB_D2_P -USB_D2_N
differential pair USB4CN26: +USB4CN26_P -USB4CN26_N
differential pair USB3CN26: +USB3CN26_P -USB3CN26_N
differential pair USB2CN25: +USB2CN25_P -USB2CN25_N
differential pair USB1CN25: +USB1CN25_P -USB1CN25_N
differential pair TD2: +TD2_P -TD2_N
differential pair TD1: +TD1_P -TD1_N
differential pair RD2: +RD2_P -RD2_N
differential pair RD1: +RD1_P -RD1_N
differential pair DDR_DQS1: +DDR_DQS1_P -DDR_DQS1_N
differential pair DDR_DQS0: +DDR_DQS0_P -DDR_DQS0_N
differential pair DDR_CLK: +DDR_CLK_P -DDR_CLK_N

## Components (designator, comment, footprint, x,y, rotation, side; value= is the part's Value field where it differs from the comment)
B1 "SW_PUSH_SMD" SWI_KNITTER_TSS644S 7.305,85.188 r270 bottom value=SW-PUSH-TSS644S
B2 "SW_PUSH_SMD" SWI_KNITTER_TSS644S 7.305,75.163 r270 bottom value=SW-PUSH-TSS644S
B3 "SW_PUSH_SMD" SWI_KNITTER_TSS644S 64.725,8.125 r270 bottom value=SW-PUSH-TSS644S
B4 "SW_PUSH_SMD" SWI_KNITTER_TSS644S 48.725,8.125 r90 bottom locked value=SW-PUSH-TSS644S
B5 "SW_PUSH_SMD" SWI_KNITTER_TSS644S 56.725,8.125 r270 bottom locked value=SW-PUSH-TSS644S
C1 "Capacitor" C0402#1 109.35,94.2 r0 top value=12pF
C2 "Capacitor" C0402#1 111.15,93.75 r90 top value=12pF
C3 "Capacitor" C0402#1 114,93.75 r90 top value=12pF
C4 "Capacitor" C0402#1 109.35,91.65 r0 top value=12pF
C5 "Capacitor" C0201_MURATA_GRM033_H0P3 31.925,90.95 r0 top value=1uF
C6 "Capacitor" C0402#1 30.425,90.725 r180 top value=1uF
C7 "Capacitor" C0402#1 42.925,89.825 r270 bottom value=100nF
C8 "Capacitor" C0402#1 44.625,90.225 r180 bottom value=100nF
C9 "Capacitor" C0402#1 29.7,89.3 r270 top value=100nF
C10 "Capacitor" C0201_MURATA_GRM033_H0P3 28.95,89.02 r270 top value=1uF
C11 "Capacitor" C0402#1 36.05,89.225 r180 top value=100nF
C12 "Capacitor" C0402#1 29.3,88.075 r0 top value=100nF
C13 "Capacitor" C0402#1 38.515,84.915 r90 top value=100nF
C14 "Capacitor" C0402#1 36.05,87.225 r180 top value=10nF
C15 "Capacitor" C0402#1 110.675,87.175 r180 top value=100nF
C16 "Capacitor" C0402#1 38.515,82.715 r270 top value=100nF
C17 "Capacitor" C0201_MURATA_GRM033_H0P3 37.715,82.715 r270 top value=1uF
C18 "Capacitor" C0201_H0P5 106.775,82.85 r90 top value=2.2uF
C19 "Capacitor" C0603 107.925,82.375 r90 top value=10uF
C20 "Capacitor" C0402#1 109.075,82.7 r90 top value=4.7uF
C21 "Capacitor" C0402#1 110,82.7 r90 top value=4.7uF
C22 "Capacitor" C0402#1 72.85,82.475 r270 top value=100nF
C23 "Capacitor" C0201_MURATA_GRM033_H0P3 73.65,82.475 r270 top value=1uF
C24 "Capacitor" C0201_MURATA_GRM033_H0P3 16.325,78.85 r0 top value=1uF
C25 "Capacitor" C0402#1 16.3,78.05 r0 top value=100nF
C26 "Capacitor" C0402#1 28.55,78.05 r180 top value=100nF
C27 "Capacitor" C0603 109.875,64.45 r0 top value=10uF
C28 "Capacitor" C0402#1 42.075,64 r0 top value=100nF
C29 "Capacitor" C0603 82.25,62.5 r180 top value=10uF
C30 "Capacitor" C0402#1 51.975,61.575 r180 top value=100nF
C31 "Capacitor" C0402#1 82.575,61.35 r0 top value=100nF
C32 "Capacitor" C0402#1 31.675,61 r180 top value=100nF
C33 "Capacitor" C0402#1 38.3,60.8 r0 top value=100nF
C34 "Capacitor" C0402#1 82.575,60.425 r0 top value=10nF
C35 "Capacitor" C0402#1 31.675,60 r180 top value=100nF
C36 "Capacitor" C0402#1 97.25,58.15 r180 top value=1uF
C37 "Capacitor" C0402#1 44.45,57.3 r90 top value=100nF
C38 "Capacitor" C0402#1 48.05,57.3 r90 top value=470pF
C39 "Capacitor" C0603 41.75,57.475 r180 top value=10uF
C40 "Capacitor" C0201_MURATA_GRM033_H0P3 47.25,57.55 r90 top value=1uF
C41 "Capacitor" C0402#1 97.25,57.225 r0 top value=100nF
C42 "Capacitor" C0402#1 103.225,56.775 r90 top value=4.7uF
C43 "Capacitor" C0402#1 104.15,56.775 r90 top value=1uF
C44 "Capacitor" C0402#1 105.075,56.775 r90 top value=100nF
C45 "Capacitor" C1206_H1P25 91.2,56.075 r180 top value=4.7uF
C46 "Capacitor" C0402#1 107.425,55.3 r270 top value=100nF
C47 "Capacitor" C0402#1 109.425,55.3 r270 top value=100nF
C48 "Capacitor" C0402#1 110.35,55.3 r270 top value=100nF
C49 "Capacitor" C0402#1 111.275,55.3 r270 top value=100nF
C50 "Capacitor" C0402#1 73.895,60.2 r270 top value=4.7uF
C51 "Capacitor" C1206_H1P25 91.2,53.825 r180 top value=4.7uF
C52 "Capacitor" C0603 87.875,53.2 r90 top value=100nF
C53 "Capacitor" C0402#1 74.825,60.225 r90 top value=100nF
C54 "Capacitor" C0402#1 83.025,53.9 r0 top value=10nF
C55 "Capacitor" C0402#1 101.125,53.9 r0 top value=10nF
C56 "Capacitor" C0402#1 86.525,53.45 r90 top value=33pF
C57 "Capacitor" C0402#1 101.325,52.55 r0 top value=100nF
C58 "Capacitor" C0402#1 101.325,51.625 r0 top value=100nF
C59 "Capacitor" C0402#1 101.325,50.7 r0 top value=100nF
C60 "Capacitor" C0201_H0P5 117.15,50.15 r180 top value=2.2uF
C61 "Capacitor" C0402#1 100.25,49.775 r180 top value=100nF
C62 "Capacitor" C0402#1 117.3,49.225 r180 top value=100nF
C63 "Capacitor" C0402#1 117.3,48.3 r180 top value=100nF
C64 "Capacitor" C0201_H0P5 117.15,47.375 r180 top value=2.2uF
C65 "Capacitor" C0402#1 101.725,45.725 r90 top value=100nF
C66 "Capacitor" C0603 66.3,45.15 r270 top value=22uF
C67 "Capacitor" C0402#1 117.3,45.375 r180 top value=100nF
C68 "Capacitor" C0402#1 101.325,44.4 r0 top value=100nF
C69 "Capacitor" C0402#1 117.3,43.375 r180 top value=100nF
C70 "Capacitor" C0402#1 89.575,42.575 r180 top value=100nF
C71 "Capacitor" C0402#1 42.075,41.675 r0 top value=100nF
C72 "Capacitor" C0603 64,41.25 r0 top value=22uF
C73 "Capacitor" C0201_H0P5 111.275,40.85 r90 top value=2.2uF
C74 "Capacitor" C0402#1 103.825,40.7 r90 top value=100nF
C75 "Capacitor" C0402#1 104.75,40.7 r90 top value=100nF
C76 "Capacitor" C0402#1 108.5,40.7 r90 top value=100nF
C77 "Capacitor" C0402#1 109.425,40.7 r90 top value=100nF
C78 "Capacitor" C0402#1 110.35,40.7 r90 top value=100nF
C79 "Capacitor" C0402#1 51.975,39.2 r180 top value=100nF
C80 "Capacitor" C0402#1 31.675,38.5 r180 top value=100nF
C81 "Capacitor" C0402#1 38.3,38.45 r0 top value=100nF
C82 "Capacitor" C0402#1 81.85,37.6 r270 top value=100nF
C83 "Capacitor" C0402#1 9,24.8 r180 top value=100nF
C84 "Capacitor" C0402#1 120.85,37.175 r270 top value=100pF
C85 "Capacitor" C0402#1 31.675,37.475 r180 top value=100nF
C86 "Capacitor" C0402#1 101.675,36.55 r270 top value=22pF
C87 "Capacitor" C0402#1 108.875,36.55 r270 top value=22pF
C88 "Capacitor" C0402#1 61.425,36.4 r90 top value=6.8pF
C89 "Capacitor" C0402#1 44.45,34.95 r90 top value=100nF
C90 "Capacitor" C0402#1 49.725,34.95 r90 top value=470pF
C91 "Capacitor" C0603 41.75,35.1 r180 top value=10uF
C92 "Capacitor" C0201_MURATA_GRM033_H0P3 50.525,34.95 r90 top value=1uF
C93 "Capacitor" C0402#1 61.425,34 r270 top value=6.8pF
C94 "Capacitor" C0402#1 81.3,33.45 r90 top value=100nF
C95 "Capacitor" C0402#1 46.125,33.6 r0 top value=6.8pF
C96 "Capacitor" C0402#1 48.1,33.6 r180 top value=6.8pF
C98 "Capacitor" C0402#1 64.375,30.625 r90 top value=6.8pF
C99 "Capacitor" C0402#1 38.275,30.55 r90 top value=4.7uF
C100 "Capacitor" C0402#1 40.625,30.55 r270 top value=4.7uF
C101 "Capacitor" C0402#1 42.625,30.55 r270 top value=4.7uF
C102 "Capacitor" C0402#1 110.025,29.85 r0 top value=100nF
C103 "Capacitor" C0402#1 62.35,29 r0 top value=6.8pF
C104 "Capacitor" C0402#1 96.325,28.9 r180 top value=100nF
C105 "Capacitor" C0402#1 85.9,28.85 r0 top value=100nF
C106 "Capacitor" C0402#1 87.55,28.85 r0 top value=100nF
C107 "Capacitor" C0402#1 89.2,28.85 r180 top value=100nF
C108 "Capacitor" C0402#1 114.4,27.9 r270 top value=100nF
C109 "Capacitor" C0402#1 115.325,27.9 r270 top value=4.7uF
C110 "Capacitor" C0603 49.175,27.325 r90 top value=22uF
C111 "Capacitor" C0603 51.975,27.325 r270 top value=22uF
C112 "Capacitor" C0603 96.65,27.775 r180 top value=10uF
C113 "Capacitor" C0603 16.15,27.175 r90 top value=22uF
C114 "Capacitor" C0603 17.4,27.175 r90 top value=22uF
C115 "Capacitor" C0603 30.5,26.475 r270 top value=22uF
C116 "Capacitor" C0603 33.3,26.475 r90 top value=22uF
C117 "Capacitor" C0402#2 28.925,90.4 r90 top value=10nF
C118 "Capacitor" C0402#1 72.525,26.175 r270 top value=100nF
C119 "Capacitor" C0402#1 75.025,26.175 r90 top value=100nF
C120 "Capacitor" C0603 46.45,25.875 r180 top value=10uF
C121 "Capacitor" C0402#1 92.325,25.875 r180 top value=100nF
C122 "Capacitor" C0402#1 12.625,25.225 r270 top value=1uF
C123 "Capacitor" C0603 17.45,24.05 r270 top value=10uF
C124 "Capacitor" C0603 78.65,24.05 r90 top value=22uF
C125 "Capacitor" C0603 35.05,24.475 r0 top value=10uF
C126 "Capacitor" C0603 49.4,23.9 r90 top value=22uF
C127 "Capacitor" C0603 52.2,23.9 r270 top value=22uF
C128 "Capacitor" C0603 29.375,22.375 r270 top value=22uF
C129 "Capacitor" C0603 32.175,22.375 r90 top value=22uF
C130 "Capacitor" C1206_H1P6 61.175,22.175 r180 top value=47uF
C131 "Capacitor" C0603 46.825,22.025 r180 top value=10uF
C132 "Capacitor" C0402#1 44.525,21.65 r180 top value=4.7uF
C133 "Capacitor" C0603 57.8,20.1 r90 top value=22uF
C134 "Capacitor" C0603 35.725,20.375 r0 top value=10uF
C135 "Capacitor" C0402#1 61.625,20.6 r180 top value=100nF
C136 "Capacitor" C1206_H1P6 75.5,18.45 r270 top value=220uF
C137 "Capacitor" C1206_H1P6 94.5,18.45 r270 top value=220uF
C138 "Capacitor" C0402#1 100.975,19.55 r90 top value=100nF
C139 "Capacitor" C0402#1 101.9,19.55 r90 top value=4.7uF
C140 "Capacitor" C0402#1 102.825,19.55 r90 top value=10nF
C141 "Capacitor" C0402#1 39.275,19.475 r90 top value=1uF
C142 "Capacitor" C0402#1 40.675,19.475 r90 top value=4.7uF
C143 "Capacitor" C0402#1 41.775,19.475 r90 top value=1uF
C144 "Capacitor" C0402#1 42.9,19.475 r90 top value=4.7uF
C145 "Capacitor" C0402#1 44.2,19.475 r90 top value=4.7uF
C146 "Capacitor" C0402#1 45.325,19.475 r90 top value=1uF
C147 "Capacitor" C0402#1 113.2,19.2 r90 top value=470pF
C148 "Capacitor" C0402#1 115.5,19.2 r90 top value=470pF
C149 "Capacitor" C0603 114.35,18.875 r90 top value=100nF
C150 "Capacitor" C0402#1 56.4,18.55 r270 top value=100nF
C151 "Capacitor" C0402#1 24.945,19.464 r180 top value=470pF
C152 "Capacitor" C0402#1 73.925,17.05 r270 top value=100nF
C153 "Capacitor" C0402#1 92.925,17.05 r270 top value=100nF
C154 "Capacitor" C0402#1 62.55,17.275 r180 top value=100nF
C155 "Capacitor" C0603 27.92,18.139 r270 top value=100nF
C156 "Capacitor" C0402#1 24.945,18.214 r180 top value=470pF
C157 "Capacitor" C0402#1 50.375,15.6 r0 top value=100nF
C158 "Capacitor" C0402#1 62.55,15.275 r180 top value=100nF
C159 "Capacitor" C0402#1 62.15,13.925 r270 top value=6.8pF
C160 "Capacitor" C0402#1 16.77,14.989 r270 top value=1uF
C161 "Capacitor" C0402#1 15.62,14.989 r90 top value=100pF
C162 "Capacitor" C1206_H1P6 24.97,13.214 r270 top value=220uF
C163 "Capacitor" C0402#1 50.375,12.75 r0 top value=100nF
C164 "Capacitor" C0402#1 62.15,12.2 r90 top value=6.8pF
C165 "Capacitor" C0402#1 50.375,11.85 r0 top value=100nF
C166 "Capacitor" C0603 14.675,12.25 r0 top value=4.7uF
C167 "Capacitor" C0603_H0P8 19.37,12.689 r270 top value=2.2nF
C168 "Capacitor" C0402#1 50.375,10.925 r0 top value=4.7uF
C169 "Capacitor" C0402#1 62.55,9.4 r180 top value=100nF
C170 "Capacitor" C0402#1 54.75,6.95 r90 top value=100nF
C171 "Capacitor" C0201_MURATA_GRM033_H0P3 75.7,40.275 r0 bottom value=1uF
C172 "Capacitor" C0603 96.775,39.5 r0 bottom value=10uF
C173 "Capacitor" C0201_MURATA_GRM033_H0P3 75.15,39.7 r180 bottom value=1uF
C174 "Capacitor" C0201_MURATA_GRM033_H0P3 70.75,38.754 r0 bottom value=1uF
C175 "Capacitor" C0201_MURATA_GRM033_H0P3 75.15,38.725 r180 bottom value=1nF
C176 "Capacitor" C0201_MURATA_GRM033_H0P3 73.375,38.675 r0 bottom value=1uF
C177 "Capacitor" C0201_MURATA_GRM033_H0P3 72.275,38.675 r0 bottom value=1uF
C178 "Capacitor" C0402#1 96.875,38.4 r0 bottom value=100nF
C179 "Capacitor" C0402#1 94.025,38.4 r180 bottom value=100nF
C180 "Capacitor" C0402#1 92.325,38.4 r0 bottom value=100nF
C181 "Capacitor" C0402#1 87.425,38.25 r180 bottom value=100nF
C182 "Capacitor" C0201_MURATA_GRM033_H0P3 76,37.925 r270 bottom value=1uF
C183 "Capacitor" C0201_MURATA_GRM033_H0P3 69.9,37.9 r270 bottom value=1uF
C184 "Capacitor" C0201_MURATA_GRM033_H0P3 74.825,37.675 r0 bottom value=1nF
C185 "Capacitor" C0201_MURATA_GRM033_H0P3 73.725,37.678 r180 bottom value=1uF
C186 "Capacitor" C0201_MURATA_GRM033_H0P3 72.3,37.625 r180 bottom value=1uF
C187 "Capacitor" C0201_MURATA_GRM033_H0P3 71.175,37.625 r180 bottom value=1uF
C188 "Capacitor" C0201_MURATA_GRM033_H0P3 74,36.525 r90 bottom value=1uF
C189 "Capacitor" C0201_MURATA_GRM033_H0P3 73.175,36.75 r180 bottom value=1uF
C190 "Capacitor" C0201_MURATA_GRM033_H0P3 71.925,36.475 r90 bottom value=1uF
C191 "Capacitor" C0201_MURATA_GRM033_H0P3 69.875,36.25 r270 bottom value=1uF
C192 "Capacitor" C0201_MURATA_GRM033_H0P3 76.05,36.225 r90 bottom value=1nF
C193 "Capacitor" C0201_MURATA_GRM033_H0P3 74.975,36 r90 bottom value=1nF
C194 "Capacitor" C0201_MURATA_GRM033_H0P3 70.975,35.975 r90 bottom value=1uF
C195 "Capacitor" C0201_MURATA_GRM033_H0P3 73.725,35.7 r180 bottom value=1uF
C196 "Capacitor" C0201_MURATA_GRM033_H0P3 72.2,35.65 r180 bottom value=1uF
C197 "Capacitor" C0201_MURATA_GRM033_H0P3 69.875,35.15 r270 bottom value=1uF
C198 "Capacitor" C0201_MURATA_GRM033_H0P3 76.05,35.125 r270 bottom value=1uF
C199 "Capacitor" C0201_MURATA_GRM033_H0P3 74.975,34.9 r270 bottom value=1uF
C200 "Capacitor" C0201_MURATA_GRM033_H0P3 74,34.875 r270 bottom value=1uF
C201 "Capacitor" C0201_MURATA_GRM033_H0P3 71,34.875 r270 bottom value=1uF
C202 "Capacitor" C0201_MURATA_GRM033_H0P3 71.9,34.825 r270 bottom value=1uF
C203 "Capacitor" C0201_MURATA_GRM033_H0P3 72.725,34.75 r0 bottom value=1uF
C204 "Capacitor" C0201_MURATA_GRM033_H0P3 74.975,33.8 r90 bottom value=1nF
C205 "Capacitor" C0201_MURATA_GRM033_H0P3 71,33.775 r270 bottom value=1uF
C206 "Capacitor" C0201_MURATA_GRM033_H0P3 76.05,33.475 r90 bottom value=1nF
C207 "Capacitor" C0201_MURATA_GRM033_H0P3 69.925,33.4 r270 bottom value=1uF
C208 "Capacitor" C0201_MURATA_GRM033_H0P3 73.225,33.6 r0 bottom value=1uF
C209 "Capacitor" C0201_MURATA_GRM033_H0P3 72,33.6 r0 bottom value=1uF
C210 "Capacitor" C0402#1 77.25,32.8 r90 bottom value=100nF
C211 "Capacitor" C0201_MURATA_GRM033_H0P3 75.475,32.65 r180 bottom value=1nF
C212 "Capacitor" C0201_MURATA_GRM033_H0P3 74.375,32.65 r0 bottom value=1uF
C213 "Capacitor" C0201_MURATA_GRM033_H0P3 73.275,32.65 r0 bottom value=1uF
C214 "Capacitor" C0201_MURATA_GRM033_H0P3 71.625,32.55 r0 bottom value=1uF
C215 "Capacitor" C0201_MURATA_GRM033_H0P3 70.525,32.55 r180 bottom value=1uF
C216 "Capacitor" C0201_H0P5 75.325,31.475 r0 bottom value=2.2uF
C217 "Capacitor" C0201_H0P5 74.025,31.475 r0 bottom value=2.2uF
C218 "Capacitor" C0402#1 95.45,30.9 r270 bottom value=100nF
C219 "Capacitor" C0201_MURATA_GRM033_H0P3 71.155,31.245 r0 bottom value=1uF
C220 "Capacitor" C0402#1 71.205,30.545 r180 bottom value=100nF
C221 "Capacitor" C0402#1 110.275,16.923 r0 bottom value=100pF
C222 "Capacitor" C1210 109.325,14.898 r0 bottom value=10uF
C223 "Capacitor" C0402#1 53.867,13.937 r270 bottom value=10nF
C224 "Capacitor" C1206_H1P6 98.775,4.75 r90 bottom value=220uF
C225 "Capacitor" C1206_H1P6 79.675,4.75 r90 bottom value=220uF
C226 "Capacitor" C0402#1 97.275,4.4 r90 bottom value=100nF
C227 "Capacitor" C0402#1 78.2,4.35 r90 bottom value=100nF
C228 "Capacitor" C0402#1 68.7,5.375 r270 bottom value=10nF
C229 "Capacitor" C0402#2 31.675,46.55 r180 top value=100pF
CART-1 "Comment" Sheetbox_6L2S 16.925,-29.775 r0 top
CN1 "Socket_FFC/FPC_1-1734248-5" CON_TE-CONNECTIVITY_1-1734248-5 20.2,93.4 r180 top
CN3 "MR01A-01211" CON_MICROSD_ATOM_MR01A-01211 127,65.5 r90 top value=Connector_uSD-Card_MR01A-01211
CN4 "RJ45_RTS-119A-12F6-GY-02" CON_RJ45_PHC_RMT-119A-12F6-GY-02 0,39 r270 top value=connector_RJ45_RMT-119A-12F6-GY-02
CN5 "USB_DUAL_TYPEA_5600-3081" CON_DUAL-USB-TYPE-A_CONEXCON_5600-3081 79,-2 r0 top value=USB_uA_5600-3081
CN6 "USB_DUAL_TYPEA_5600-3081" CON_DUAL-USB-TYPE-A_CONEXCON_5600-3081 98,-2 r0 top locked value=USB_uA_5600-3081
CN7 "USB_TYPE_C_Receptacle" CON_USB-TYPEC_MOLEX_2012670005 114.725,4.85 r0 top value=USB_C_2012670005
CN8 "Header 20x2" CON_SAMTEC_TSW-120-07-G-D 65.75,93.5 r0 bottom
CN9 "Header 4x1" CON_SAMTEC_TSW-104-07-G-S 125,46 r90 bottom
CN10 "USB_uB_105017.0001" CON_USBMICROB_MOLEX_105017-0001_H2P90 127,35.425 r270 bottom value=USB_uB_105017-0001
CN11 "Header 2x1" CON_MOLEX_53047-0210 6.75,24.2 r270 bottom
CN12 "USB_TYPE_C_Receptacle" CON_USB-TYPEC_MOLEX_2012670005 4.825,14.325 r270 top value=USB_C_2012670005
CN13 "Header 4x1" CON_SAMTEC_TSW-104-07-G-S 125,15 r90 bottom
CN14 "Header 7x2" CON_SAMTEC_TSW-107-07-X-D 18.5,5.55 r0 bottom value="Jumper_Header 7x2"
CN15 "RJ45_RTS-119A-12F6-GY-02" CON_RJ45_PHC_RMT-119A-12F6-GY-02 0,61.53 r270 top value=connector_RJ45_RMT-119A-12F6-GY-02
CN16 "5051104091" CON_MOLEX_5051104091 66.775,62 r180 bottom value=Socket_FFC/FPC_5051104091
D1 "BAT60JFILM" DIO_SOD323 98.175,62.575 r180 top
D2 "STPS1L40M" DIO_DO216-AA 90.35,59.6 r90 top
D3 "BAT60JFILM" DIO_SOD323 98.175,60.65 r180 top
D4 "BAT60JFILM" DIO_SOD323 105.925,18.65 r270 top
D5 "SCHOTTKY_1A_2K" DIO_SOD523_1A_2K 26.52,18.164 r90 top value=BAT54KFILM
Designator1 "Comment" MIRE_PLACE_SMD_0P8MM 6.1,87.975 r0 top
Designator2 "Comment" MIRE_PLACE_SMD_0P8MM 118.45,80.325 r0 top
Designator3 "Comment" MIRE_PLACE_SMD_0P8MM 121.65,11.025 r0 top
Designator4 "Comment" MIRE_PLACE_SMD_0P8MM 119.025,80.825 r180 bottom
Designator5 "Comment" MIRE_PLACE_SMD_0P8MM 5.875,20.5 r180 bottom
Designator6 "Comment" MIRE_PLACE_SMD_0P8MM 121.8,10.95 r180 bottom
HW2 "STICKER_BOARD" STICKER_BOARD_25X9 111.625,91.95 r180 bottom value="Sticker board"
HW3 "STICKER_PRODUCT" STICKER_PRODUCT_25X9 93.099,72.875 r0 top value="Sticker product"
L1 "Inductor" IND_0402_MURATA_LQW15AN2N4C00X 118.525,94.2 r0 top value=2.4nH
L2 "Inductor" L0603 110.575,85.25 r270 top value=2.2uH
L3 "Inductor" L1210_LQH 86.225,63.25 r0 top value=4.7uH
L4 "BEAD" L0603 41.475,56.025 r180 top value="600R @ 100MHz"
L5 "BEAD" L0603 41.475,33.675 r180 top value="600R @ 100MHz"
L6 "IND_1uH_42mohm_3.2A" IND_2520_TOKO_DFE252012P 46.425,27.775 r0 top value=1uH
L7 "IND_1uH_42mohm_3.2A" IND_2520_TOKO_DFE252012P 35.8,26.95 r90 top value=1uH
L8 "Inductor" IND_4025_WURTH_74404043022A 20.4,25.7 r90 top value=2.2uH
L9 "IND_1uH_42mohm_3.2A" IND_2520_TOKO_DFE252012P 46.475,23.9 r0 top value=1uH
L11 "IND_1uH_42mohm_3.2A" IND_2520_TOKO_DFE252012P 35.1,22.425 r180 top value=1uH
L12 "BEAD" FIL_0603_H0P65 61.975,19.35 r0 top value="26R @ 100Mhz"
LD1 "LED_green" LED_0603_GREEN 7.2,14.15 r180 bottom value=GREEN
LD2 "LED_red" LED_0603_RED 89.4,18.3 r0 bottom value=RED
LD3 "LED_blue" LED_0603_SMD-B_BLUE_H0P4 3.305,86.213 r90 bottom value=BLUE
LD4 "LED_red" LED_0603_RED 3.205,76.913 r90 bottom value=RED
LD5 "LD_BICOLOR_VCC" LED_BI-GR_CMD67-22 122.025,28.35 r90 bottom
LD6 "LED_orange" LED_0603_ORANGE_H0P4 44.525,8.425 r90 bottom value=ORANGE
LD7 "LED_green" LED_0603_GREEN 52.75,8.425 r90 bottom value=GREEN
Q1 "STL40DN3LLH5" PowerFLAT_5x6 105.275,34.325 r0 top
Q2 "STL40DN3LLH5" PowerFLAT_5x6 112.4,34.325 r0 top
Q3 "STL11N3LLH6" MOS_POWERFLAT_3P3X3P3_P065 21.845,13.064 r180 top
R1 "Resistor" R0402#1 112.675,94.2 r180 top value=0R
R2 "Resistor" R0402#1 109.8,92.975 r270 top value=0R
R3 "Resistor" R0402#1 39.765,87.265 r90 top value=10K
R4 "Resistor" R0402#1 40.84,87.265 r90 top value=10K
R5 "Resistor" R0402#1 36.05,88.225 r180 top value=10K
R6 "Resistor" R0402#1 42.14,84.915 r270 top value=10K
R7 "Resistor" R0402#1 66.475,86.8 r270 top value=10K
R8 "Resistor" R0402#1 67.55,86.8 r270 top value=10K
R9 "Resistor" R0402#1 68.625,86.8 r270 top value=10K
R10 "Resistor" R0402#1 69.925,86.8 r270 top value=0R
R11 "Resistor" R0402#1 71,86.8 r270 top value=0R
R12 "Resistor" R0402#1 63.2,83.6 r0 top value=0R
R13 "Resistor" R0402#1 40.54,80.415 r90 top value=4K7
R14 "Resistor" R0402#1 101.1,82.7 r90 top value=47K
R15 "Resistor" R0402#1 102.175,82.7 r90 top value=47K
R16 "Resistor" R0402#1 103.25,82.7 r90 top value=47K
R17 "Resistor" R0402#1 104.325,82.7 r90 top value=47K
R18 "Resistor" R0402#1 105.4,82.7 r90 top value=47K
R19 "Resistor" R0402#1 63.2,82.525 r0 top value=0R
R20 "Resistor" R0402#1 31.975,76.575 r270 top value=0R
R21 "Resistor" R0402#1 33.05,76.575 r270 top value=0R
R22 "Resistor" R0402#1 16.325,75.65 r180 top value=10K
R23 "Resistor" R0402#1 28.55,75.65 r0 top value=10K
R24 "Resistor" R0402#1 31.675,68.15 r180 top value=10K
R25 "Resistor" R0402#1 46.8,68.025 r0 top value=10K
R26 "Resistor" R0402#1 46.8,66.95 r0 top value=10K
R27 "Resistor" R0402#1 31.675,66.3 r180 top value=270R
R28 "Resistor" R0402#1 46.275,65.55 r270 top value=0R
R29 "Resistor" R0402#1 47.35,65.55 r90 top value=10K
R30 "Resistor" R0402#1 48.425,65.55 r270 top value=0R
R31 "Resistor" R0402#1 51.975,65.8 r0 top value=1K5
R32 "Resistor" R0402#1 51.975,64.725 r0 top value=10K
R33 "Resistor" R0402#1 102.375,63.775 r270 top value=10K
R34 "Resistor" R0402#1 103.45,63.775 r90 top value=10K
R35 "Resistor" R0603 82.25,63.9 r0 top value=0R
R36 "Resistor" R0402#1 51.975,63.65 r180 top value=33R
R37 "Resistor" R0402#1 42.075,63 r180 top value=49R9
R38 "Resistor" R0402#1 51.975,62.575 r0 top value=10K
R39 "Resistor" R0402#1 42.075,61.925 r180 top value=49R9
R40 "Resistor" R0402#1 42.075,60.85 r180 top value=49R9
R41 "Resistor" R0402#1 51.975,60.575 r180 top value=33R
R42 "Resistor" R0402#1 42.075,59.775 r180 top value=49R9
R43 "Resistor" R0402#1 51.975,59.5 r0 top value=10K
R44 "Resistor" R0402#1 82.575,59.425 r0 top value=100K
R45 "Resistor" R0402#1 97.25,59.15 r0 top value=0R
R46 "Resistor" R0402#1 109.9,58.5 r90 top value=100K
R47 "Resistor" R0402#1 42.075,58.7 r180 top value=12K1
R48 "Resistor" R0402#1 51.975,58.425 r0 top value=10K
R49 "Resistor" R0603 82.25,57.525 r0 top value=10R
R50 "Resistor" R0402#1 46.375,57.3 r90 top value=22R
R51 "Resistor" R0402#1 51.975,57.35 r180 top value=33R
R52 "Resistor" R0402#1 31.675,56.75 r180 top value=270R
R53 "Resistor" R0402#1 86.225,56.525 r0 top value=4K7
R54 "Resistor" R0402#1 108.425,55.3 r90 top value=0R
R55 "Resistor" R0402#1 112.275,55.3 r90 top value=0R
R56 "Resistor" R0402#1 113.775,55.3 r270 top value=0R
R57 "Resistor" R0402#1 86.225,55.45 r0 top value=0R
R58 "Resistor" R0402#1 59.2,63.25 r90 top value=4K7
R59 "Resistor" R0402#1 61.325,65.325 r270 top value=4K7
R60 "Resistor" R0402#1 84.95,53.9 r180 top value=0R
R61 "Resistor" R0402#1 117.3,51.225 r0 top value=0R
R62 "Resistor" R0402#1 96.45,48.7 r90 top value=2K4
R63 "Resistor" R0402#1 97.525,48.7 r90 top value=2K4
R64 "Resistor" R0402#1 81.7,48.725 r180 top value=0R
R65 "Resistor" R0402#1 98.525,47.925 r270 top value=10K
R66 "Resistor" R0402#1 117.3,46.375 r180 top value=3K
R68 "Resistor" R0402#1 100.725,45.725 r270 top value=0R
R69 "Resistor" R0402#1 46.8,45.65 r0 top value=10K
R70 "Resistor" R0402#1 31.675,45.6 r180 top value=10K
R71 "Resistor" R0402#1 37.95,45.3 r180 top value=1K5
R72 "Resistor" R0402#1 94.075,45.125 r180 top value=10K
R73 "Resistor" R0402#1 46.8,44.575 r0 top value=10K
R74 "Resistor" R0402#1 117.3,44.375 r180 top value=100R
R75 "Resistor" R0402#1 37.95,44.2 r180 top value=1K5
R76 "Resistor" R0402#1 31.675,43.75 r180 top value=270R
R77 "Resistor" R0402#1 46.275,43.175 r270 top value=0R
R78 "Resistor" R0402#1 47.35,43.175 r90 top value=10K
R79 "Resistor" R0402#1 48.425,43.175 r270 top value=33R
R80 "Resistor" R0402#1 51.975,43.425 r0 top value=1K5
R81 "Resistor" R0402#1 101.325,43.4 r180 top value=0R
R82 "Resistor" R0402#1 61.425,42.875 r180 top value=1K5
R83 "Resistor" R0402#1 51.975,42.35 r0 top value=10K
R84 "Resistor" R0402#1 101.325,42.325 r0 top value=10K
R85 "Resistor" R0402#1 61.425,41.375 r0 top value=0R
R86 "Resistor" R0402#1 51.975,41.275 r180 top value=33R
R87 "Resistor" R0402#1 101.325,41.25 r0 top value=4K7
R88 "Resistor" R0402#1 105.75,40.7 r270 top value=0R
R89 "Resistor" R0402#1 106.825,40.7 r90 top value=4K7
R90 "Resistor" R0402#1 112.275,40.7 r270 top value=0R
R91 "Resistor" R0402#1 113.35,40.7 r90 top value=0R
R92 "Resistor" R0402#1 42.075,40.625 r180 top value=49R9
R93 "Resistor" R0402#1 51.975,40.2 r0 top value=10K
R94 "Resistor" R0402#1 101.325,40.175 r0 top value=4K7
R95 "Resistor" R0402#1 42.075,39.55 r180 top value=49R9
R96 "Resistor" R0402#1 58.825,38.95 r180 top value=0R
R97 "Resistor" R0402#1 42.075,38.475 r180 top value=49R9
R98 "Resistor" R0402#1 51.975,38.2 r180 top value=33R
R99 "Resistor" R0402#1 42.075,37.4 r180 top value=49R9
R100 "Resistor" R0402#1 51.975,37.125 r0 top value=10K
R101 "Resistor" R0402#1 42.075,36.325 r180 top value=12K1
R102 "Resistor" R0402#1 51.975,36.05 r0 top value=10K
R103 "Resistor" R0402#1 62.725,35.95 r180 top value=0R
R104 "Resistor" R0402#1 45.5,34.95 r90 top value=0R
R105 "Resistor" R0402#1 46.575,34.95 r90 top value=0R
R106 "Resistor" R0402#1 47.65,34.95 r90 top value=0R
R107 "Resistor" R0402#1 48.725,34.95 r90 top value=22R
R108 "Resistor" R0402#1 57.825,35.15 r180 top value=1K5
R109 "Resistor" R0402#1 51.975,34.975 r180 top value=33R
R110 "Resistor" R0402#1 31.675,34.25 r180 top value=270R
R111 "Resistor" R0603 116.15,32.425 r90 top value=22mR
R112 "Resistor" R0402#1 80.975,31.8 r180 top value=240R
R113 "Resistor" R0603 39.45,30.875 r90 top value=100mR
R114 "Resistor" R0402#1 36.4,30.55 r270 top value=0R
R115 "Resistor" R0402#1 41.625,30.55 r270 top value=0R
R117 "Resistor" R0402#1 120.075,29.1 r180 top value=330R
R120 "Resistor" R0402#1 99.575,27.925 r90 top value=1K5
R121 "Resistor" R0402#1 100.65,27.925 r270 top value=1K5
R123 "Resistor" R0603 50.575,27.325 r270 top value=0R
R124 "Resistor" R0603 53.375,27.325 r270 top value=100mR
R125 "Resistor" R0402#1 120.075,27.6 r180 top value=330R
R126 "Resistor" R0603 29.1,26.475 r270 top value=50mR
R127 "Resistor" R0603 31.9,26.475 r270 top value=0R
R128 "Resistor" R0402#1 73.475,26.175 r270 top value=3K
R129 "Resistor" R0603 105.625,24.45 r0 top value=13K
R131 "Resistor" R0603 50.8,23.9 r270 top value=0R
R132 "Resistor" R0603 53.6,23.9 r270 top value=50mR
R133 "Resistor" R0402#1 71.775,23.475 r0 top value=0R
R134 "Resistor" R0603 105.625,23.025 r180 top value=2K
R135 "Resistor" R0402#1 11.475,22.875 r270 top value=75K
R136 "Resistor" R0402#1 12.525,22.875 r90 top value=24K
R137 "Resistor" R0603 27.975,22.375 r270 top value=100mR
R138 "Resistor" R0603 30.775,22.375 r270 top value=0R
R140 "Resistor" R0402#1 37.475,20.025 r90 top value=0R
R141 "Resistor" R0402#1 103.825,19.55 r270 top value=10K
R142 "Resistor" R0603 108.025,18.875 r270 top value=33K
R143 "Resistor" R0603 109.475,18.875 r90 top value=8K2
R144 "Resistor" R0402#1 18.72,20.614 r180 top value=47K
R145 "Resistor" R0402#1 18.72,19.539 r0 top value=5K1
R146 "Resistor" R0402#1 62.55,16.275 r180 top value=12K
R147 "Resistor" R0402#1 18.72,18.139 r0 top value=5K1
R148 "Resistor" R0402#1 24.945,17.214 r180 top value=2K4
R149 "Resistor" R0402#1 18.72,17.089 r180 top value=47K
R150 "Resistor" R0402#1 24.945,16.139 r0 top value=10K
R151 "Resistor" R0603 18.17,14.989 r270 top value=0R
R152 "Resistor" R0402#1 9.425,14.15 r0 bottom value=330R
R153 "Resistor" R0402#1 45.55,8.025 r0 top value=1K
R154 "Resistor" R0402#1 45.55,9.575 r0 top value=1K
R155 "Resistor" R0402#1 45.55,10.925 r0 top value=1K
R156 "Resistor" R0402#1 62.55,8.4 r180 top value=100K
R157 "Resistor" R0402#1 62.55,7.325 r180 top value=1K
R158 "Resistor" R0402#1 53.425,7.275 r0 top value=100K
R159 "Resistor" R0402#1 56.075,7.275 r180 top value=100K
R160 "Resistor" R0402#1 57.475,6.95 r90 top value=100K
R161 "Resistor" R0402#1 58.55,6.95 r270 top value=100K
R162 "Resistor" R0402#1 59.625,6.95 r90 top value=10K
R163 "Resistor" R0402#1 60.7,6.95 r270 top value=10K
R164 "Resistor" R0402#1 53.425,6.2 r180 top value=100K
R165 "Resistor" R0402#1 56.075,6.2 r0 top value=100K
R166 "Resistor" R0402#1 53.425,5.125 r0 top value=0R
R167 "Resistor" R0402#1 56.075,5.125 r180 top value=0R
R168 "Resistor" R0402#1 19,92.15 r180 bottom value=1K5
R169 "Resistor" R0402#1 14.25,92.15 r180 bottom value=1K5
R170 "Resistor" R0402#1 21.3,89.65 r270 bottom value=1K
R171 "Resistor" R0402#1 16.625,89.55 r270 bottom value=1K
R172 "Resistor" R0402#1 3.305,83.938 r270 bottom value=680R
R173 "Resistor" R0402#1 11.18,81.288 r270 bottom value=100R
R174 "Resistor" R0402#1 3.205,74.438 r270 bottom value=1K
R175 "Resistor" R0402#1 11.425,71.35 r90 bottom value=100R
R176 "Resistor" R0402#1 89.85,38.275 r90 bottom value=10K
R177 "Resistor" R0402#1 92.175,32.525 r90 bottom value=100R
R178 "Resistor" R0402#1 89.475,29.525 r90 bottom value=10K
R179 "Resistor" R0402#1 90.625,29.475 r90 bottom value=240R
R180 "Resistor" R0402#1 52.692,13.937 r90 bottom value=10K
R181 "Resistor" R0402#1 48.475,13.85 r0 bottom value=1K
R182 "Resistor" R0402#1 46.725,13.85 r180 bottom value=100R
R183 "Resistor" R0402#1 52.75,5.825 r90 bottom value=330R
R184 "Resistor" R0402#1 44.525,5.825 r90 bottom value=680R
R185 "Resistor" R0603 17.075,12.25 r0 top value=1R
R186 "Resistor" R0402#1 18.725,22 r0 top value=560R
R187 "Resistor" R0402#1 105.3,21.775 r0 top value=10K
R188 "Resistor" R0402#1 84.3,24.568 r180 top value=0R
R189 "Resistor" R0402#1 84.3,23.518 r180 top value=0R
R190 "Resistor" R0402#2 113.275,86.75 r90 top value=0R
R191 "Resistor" R0402#2 9,25.825 r180 top value=0R
R192 "Resistor" R0402#2 62.45,37.725 r180 top value=0R
SW1 "76SB04ST" SWI_GRAYHILL-INC_76SB04ST 36.55,8.675 r180 bottom
TP1 "Test Point" TP_SMD_1MM 98.75,95.375 r90 top
TP2 "Test Point" TP_SMD_1MM 101.375,95.1 r90 top
TP3 "Test Point" TP_SMD_1MM 104,95 r90 top
TP4 "Test Point" TP_SMD_1MM 107,95 r90 top
TP5 "Test Point" TP_SMD_1MM 99.5,92.75 r90 top
TP6 "Test Point" TP_SMD_1MM 102.5,92.75 r0 top
TP7 "Test Point" TP_SMD_1MM 105.5,92.75 r90 top
TP8 "Test Point" TP_SMD_1MM 99.5,89.75 r90 top
TP9 "Test Point" TP_SMD_1MM 93.425,89.025 r0 top
TP10 "Test Point" TP_SMD_1MM 44.823,84.75 r90 top
TP11 "Test Point" TP_SMD_1MM 96.5,88.25 r90 top
TP12 "Test Point" TP_SMD_1MM 25.3,87.45 r90 top
TP13 "Test Point" TP_SMD_1MM 12,86.95 r90 top
TP14 "Test Point" TP_SMD_1MM 99.5,86.75 r90 top
TP15 "Test Point" TP_SMD_1MM 114.725,86.35 r90 top
TP16 "Test Point" TP_SMD_1MM 31,85.5 r90 top
TP17 "Test Point" TP_SMD_1MM 9.5,85.45 r90 top
TP18 "Test Point" TP_SMD_1MM 96.5,85.25 r90 top
TP19 "Test Point" TP_SMD_1MM 44.823,81.525 r90 top
TP20 "Test Point" TP_SMD_1MM 34,84 r90 top
TP21 "Test Point" TP_SMD_1MM 12,83.95 r90 top
TP22 "Test Point" TP_SMD_1MM 99.5,83.75 r90 top
TP23 "Test Point" TP_SMD_1MM 59.1,82.525 r90 top
TP24 "Test Point" TP_SMD_1MM 31,82.5 r90 top
TP25 "Test Point" TP_SMD_1MM 9.5,82.45 r90 top
TP26 "Test Point" TP_SMD_1MM 34,81 r90 top
TP27 "Test Point" TP_SMD_1MM 99.5,81 r90 top
TP28 "Test Point" TP_SMD_1MM 12,80.95 r90 top
TP29 "Test Point" TP_SMD_1MM 52.2,17.5 r270 top
TP30 "Test Point" TP_SMD_1MM 106.975,79.675 r90 top
TP31 "Test Point" TP_SMD_1MM 31,79.5 r90 top
TP32 "Test Point" TP_SMD_1MM 9.5,79.45 r90 top
TP33 "Test Point" TP_SMD_1MM 72.525,73.45 r90 top
TP34 "Test Point" TP_SMD_1MM 65.95,73.675 r90 top
TP35 "Test Point" TP_SMD_1MM 70.975,70.8 r90 top
TP36 "Test Point" TP_SMD_1MM 67.925,71.45 r90 top
TP37 "Test Point" TP_SMD_1MM 59.425,67.925 r90 top
TP38 "Test Point" TP_SMD_1MM 117.6,55.675 r180 top
TP39 "Test Point" TP_SMD_1MM 120.75,53.9 r180 top
TP40 "Test Point" TP_SMD_1MM 58.45,66.025 r90 top
TP41 "Test Point" TP_SMD_1MM 63.145,66.125 r90 top
TP42 "Test Point" TP_SMD_1MM 57.625,67.925 r90 top
TP43 "Test Point" TP_SMD_1MM 63.145,67.975 r180 top
TP44 "Test Point" TP_SMD_1MM 95.725,45.9 r270 top
TP45 "Test Point" TP_SMD_1MM 92.75,43.25 r0 top
TP46 "Test Point" TP_SMD_1MM 95.4,43.25 r0 top
TP47 "Test Point" TP_SMD_1MM 108.25,38.75 r180 top
TP48 "Test Point" TP_SMD_1MM 115.45,38.75 r180 top
TP49 "Test Point" TP_SMD_1MM 38.35,33.375 r90 top
TP50 "Test Point" TP_SMD_1MM 56.825,31.675 r90 top
TP51 "Test Point" TP_SMD_1MM 101.3,30.15 r180 top
TP52 "Test Point" TP_SMD_1MM 104.9,29.275 r180 top
TP53 "Test Point" TP_SMD_1MM 112.375,28.325 r180 top
TP54 "Test Point" TP_SMD_1MM 58.4,27.3 r90 top
TP55 "Test Point" TP_SMD_1MM 107.6,26.55 r180 top
TP56 "Test Point" TP_SMD_1MM 96.075,26.1 r180 top
TP57 "Test Point" TP_SMD_1MM 66.7,25.8 r90 top
TP58 "Test Point" TP_SMD_1MM 93.625,24.45 r180 top
TP59 "Test Point" TP_SMD_1MM 96.075,23.125 r180 top
TP61 "Test Point" TP_SMD_1MM 82.1,21.975 r90 top
TP62 "Test Point" TP_SMD_1MM 11.475,20.75 r90 top
TP63 "Test Point" TP_SMD_1MM 78.55,20.65 r180 top
TP64 "Test Point" TP_SMD_1MM 111.125,19.65 r270 top
TP65 "Test Point" TP_SMD_1MM 117.675,19.65 r270 top
TP66 "Test Point" TP_SMD_1MM 48.425,19.625 r90 top
TP67 "Test Point" TP_SMD_1MM 30.875,18.275 r90 top
TP68 "Test Point" TP_SMD_2MM 12.8,18.225 r180 top
TP69 "Test Point" TP_SMD_1MM 37.75,16.9 r90 top
TP70 "Test Point" TP_SMD_1MM 40.925,16.9 r180 top
TP71 "Test Point" TP_SMD_1MM 43.5,16.9 r90 top
TP72 "Test Point" TP_SMD_1MM 45.987,16.875 r0 top
TP73 "Test Point" TP_SMD_1MM 8.875,20.825 r270 top
TP74 "Test Point" TP_SMD_1MM 108.575,13.7 r180 top
TP75 "Test Point" TP_SMD_1MM 119.511,13.303 r180 top
TP76 "Test Point" TP_SMD_2MM 15.825,18.3 r180 top
TP77 "Test Point" TP_SMD_1MM 12.25,15.625 r180 top
TR1 "BSN20" MOS_SOT23 19,89.65 r0 bottom value=FDV301N
TR2 "BSN20" MOS_SOT23 14.25,89.65 r0 bottom value=FDV301N
U1 "LBEE5KL1DX-883" MOD_WLAN-BT_MURATA_LBEE5KL1DX-883 105.375,88 r180 top value=LBEE5KL1DX-977
U2 "STMIPID02" ICC_VFBGA49_3X3_P040 32.775,88.55 r270 top value=STMIPID02/TR
U3 "SN74LVC2T45DCUT" ICC_VSSOP8_DCU_R-PDSO-G8_2X2P30_P050 40.29,83.815 r0 top
U4 "SN74AVC16T245" ICC_TVSOP48_9P8X6P6_P040 22.475,80.25 r270 top
U5 "MCP23017" ICC_QFN28-EPAD_6X6_P065 68.625,81.375 r90 top value=MCP23017T-E/ML
U6 "EMIF06-MSD02N16" ESD_UQFN16L-EPAD_3P5X1P2_P040 106.45,63.875 r270 top
U7 "LAN8742A-CZ-TR" ICC_VQFN24-EPAD_4X4_P050 46.325,61.4 r90 top
U8 "USBLC6-4SC6" ESD_SOT23-6L 34.725,60.8 r270 top
U9 "STLD40DPUR" ICC_QFN8-EPAD_3X3_P065 86.475,59.25 r270 top
U10 "ESD-TRANSIL" ESD_ST0201 110.875,58.625 r270 top value=ESDALC6V1-1U2
U11 "LD3985M33R" REG_SOT23-5L 100.475,56.275 r270 top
